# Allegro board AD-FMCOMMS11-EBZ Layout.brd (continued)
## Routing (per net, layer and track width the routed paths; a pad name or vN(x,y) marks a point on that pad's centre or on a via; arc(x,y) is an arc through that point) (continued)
AVDD1P3_ADC: length 33.7
  TOP w0.305: U101.C14 v1(50.01,55.58) U101.D14 v1(50.41,55.18) U101.D13 v1(50.41,54.38) U101.D12 v1(50.81,53.98) U101.E12 v1(51.61,53.98) U101.F12 v1(52.41,53.98) U101.G12 v1(53.21,53.98) U101.H12 v1(54.01,53.98) U101.J12 ; U101.A4 v1(48.41,47.98) U101.B5 v1(49.21,48.78) U101.C6 v1(50.01,49.58) U101.D7 v1(50.81,49.98) U101.E7 v1(51.61,49.98) U101.F7 v1(52.41,49.98) U101.G7 v1(53.21,49.98) U101.H7 v1(54.01,49.98) U101.J7
  TOP w0.406: 76.7,60.44 C234.1 77.36,59.78
  TOP w0.635: 76.18,64.86 TP12.1 75.44,64.12 ; 77.53,63.1 E23.2 76.61,64.1 ; C229.1 76.8,62.76 ; C229.1 76.8,60.86 ; C229.1 77.7,61.81
  BOTTOM w0.305: 50.48,55.58 v1(50.01,55.58) 49.96,55.52 C287.1 ; 50.48,55.58 C300.1 ; 50.48,55.58 50.48,55.24 v1(50.41,55.18) 50.36,55.12 C294.1 50.36,54.44 ; 50.36,54.44 v1(50.41,54.38) 50.41,53.99 50.4,53.98 ; 50.36,54.44 C279.1 50.4,53.98 ; v1(49.21,48.78) 49.21,48.79 49.34,48.92 C262.1 ; C275.1 48.13,47.7 v1(48.41,47.98) 48.59,48.16 C272.1 ; 50.4,53.98 v1(50.81,53.98) 50.83,54 C303.1 51.59,54 v1(51.61,53.98) 51.63,54 C305.1 52.39,54 v1(52.41,53.98) 52.43,54 C297.1 53.19,54 v1(53.21,53.98) 53.23,54 C307.1 53.99,54 v1(54.01,53.98) 54.03,54 C283.1 ; v1(50.81,49.98) 50.86,49.93 C198.1 51.57,49.93 v1(51.61,49.98) 51.66,49.93 C200.1 52.37,49.93 v1(52.41,49.98) 52.46,49.93 C290.1 53.17,49.93 v1(53.21,49.98) 53.26,49.93 C268.1 53.97,49.93 v1(54.01,49.98) 54.03,50 C258.1
  vias: v3(76.58,60.67) v3(77.22,60.67) v3(77.85,62.32) v3(77.85,61.68) v3(77.85,61.05) v3(77.85,60.41) v3(77.85,59.78)
AVDD2P5_ADC: length 35.6
  TOP w0.305: U101.A6 v1(48.41,49.58) U101.B7 v1(49.21,50.38) U101.C8 v1(50.01,50.78) U101.D8 v1(50.81,50.78) U101.E8 v1(51.61,50.78) U101.F8 v1(52.41,50.78) U101.G8 v1(53.21,50.78) U101.H8 v1(54.01,50.78) U101.J8 ; v3(43.73,47.39) 44.14,47.39 44.32,47.2 TP17.1 ; U101.A14 v1(48.01,55.18) U101.A13 U101.B12 v1(49.21,53.58) U101.C11 v1(50.01,53.18) U101.D11 v1(50.81,53.18) U101.E11 v1(51.61,53.18) U101.F11 v1(52.41,53.18) U101.G11 v1(53.21,53.18) U101.H11 v1(54.01,53.18) U101.J11
  BOTTOM w0.305: 51.54,53.11 C264.1 52.34,53.11 ; 51.54,53.11 C261.1 50.88,53.11 ; 51.54,53.11 v1(51.61,53.18) ; C304.1 48.07,55.12 v1(48.01,55.18) 48.07,55.24 C278.1 ; 53.28,53.11 v1(53.21,53.18) 53.14,53.11 ; 53.28,53.11 C270.1 53.94,53.11 ; 53.28,53.11 53.14,53.11 ; 49.94,53.11 v1(50.01,53.18) 50.08,53.11 ; 49.94,53.11 50.08,53.11 ; 49.94,53.11 C257.1 ; 50.74,53.11 v1(50.81,53.18) 50.88,53.11 ; 50.74,53.11 50.88,53.11 ; 50.74,53.11 C259.1 50.08,53.11 ; v1(49.21,50.38) C308.1 ; 54.08,53.11 53.94,53.11 ; 54.08,53.11 v1(54.01,53.18) 53.94,53.11 ; 54.08,53.11 C274.1 ; 52.34,53.11 v1(52.41,53.18) 52.48,53.11 ; 52.34,53.11 52.48,53.11 ; 52.48,53.11 C267.1 53.14,53.11 ; C302.1 54.31,50.78 v1(54.01,50.78) 53.64,50.78 C299.1 53.55,50.78 v1(53.21,50.78) 52.88,50.78 C296.1 52.79,50.78 v1(52.41,50.78) 52.11,50.78 C293.1 52.03,50.78 v1(51.61,50.78) 51.35,50.78 C289.1 51.26,50.78 v1(50.81,50.78) 50.59,50.78 C285.1 50.5,50.78 v1(50.01,50.78) 49.83,50.78 C281.1 ; v1(48.41,49.58) 48.16,49.58 C306.1 ; C309.1 49.05,53.74 v1(49.21,53.58)
  BOTTOM w0.508: 42.79,47.18 C256.1 ; C256.1 43.45,47.84 ; C256.1 42.79,48.5
  BOTTOM w0.635: C253.1 43.14,46.89 ; C253.1 44.04,45.93 ; C253.1 43.14,44.98
  BOTTOM w0.762: 41.21,44.39 E30.2 42.14,43.39
  vias: v3(42.97,48.66) v3(43.73,48.66) v3(43.73,48.02)
AVDD3P3_4355: length 19.2
  TOP w0.305: 35.18,31.18 TP23.1 34.44,30.44 ; v1(41.53,33.49) 41.78,33.23 41.78,33.04 C329.1 ; C331.1 42.35,37.36 v1(42.54,37.55)
  TOP w0.508: 33.5,27.63 C160.1 ; C160.1 34.82,27.63 ; C160.1 34.16,28.29
  TOP w0.635: E18.2 33.25,30.44 ; E18.2 32.32,29.45 ; E18.2 32.32,31.43 ; 32.26,28.89 C153.1 33.21,27.99
  BOTTOM w0.203: v1(38.36,38.94) 38.35,38.94 U18.5
  BOTTOM w0.254: v1(44.32,38.31) L14.2 ; C36.1 45.87,31.86 v1(45.47,31.46) L15.2 ; L16.2 v1(43.62,29.61) 43.23,29.22 C13.1 ; v1(44.32,35.76) L13.2
  BOTTOM w0.305: U18.10 41.12,36.77 C332.1 41.92,37.55 v1(42.54,37.55) ; U18.16 41.25,33.77 v1(41.53,33.49) ; C315.1 44.32,35.2 v1(44.32,35.76) ; C314.1 v1(44.32,38.31)
  BOTTOM w0.508: C330.1 C329.1 41.53,33.3 v1(41.53,33.49)
  vias: v3(33.53,28.79) v3(34.16,28.79) v3(34.8,28.79)
DVDD1P3_ADC: length 19
  TOP w0.305: U101.D1 v1(50.41,45.58) U101.D2 v1(50.41,46.38) U101.D3 ; U101.H1 v1(53.61,45.58) U101.H2 v1(53.61,46.38) U101.H3 ; U101.K1 v1(55.21,45.58) U101.K2 ; U101.F1 v1(52.01,45.58) U101.F2 v1(52.01,46.38) U101.F3
  BOTTOM w0.305: 51.88,46.51 v1(52.01,46.38) 51.88,46.25 ; 51.88,46.51 51.88,46.25 ; 51.88,46.51 C273.1 ; 51.88,46.25 C277.1 51.88,45.71 ; C295.1 53.53,46.46 ; 53.53,46.46 53.53,46.3 ; 53.53,46.46 v1(53.61,46.38) 53.53,46.3 ; 51.88,45.71 v1(52.01,45.58) 51.88,45.45 ; 51.88,45.71 51.88,45.45 ; 53.53,45.66 C298.1 53.53,46.3 ; 53.53,45.66 53.53,45.5 ; 53.53,45.66 v1(53.61,45.58) 53.53,45.5 ; C284.1 50.36,46.44 v1(50.41,46.38) 50.36,46.32 C288.1 50.36,45.64 v1(50.41,45.58) 50.36,45.52 C292.1 ; 51.88,45.45 C280.1 ; 53.53,45.5 C301.1 ; C269.1 55.21,45.2 v1(55.21,45.58) 55.21,45.9 C266.1
  BOTTOM w0.508: 63.49,54.16 C236.1 ; C236.1 63.49,55.49 ; C236.1 64.15,54.82
  BOTTOM w0.635: 66.48,54.34 E25.2 ; E25.2 66.48,56.32 ; E25.2 65.56,55.33 ; 64.49,56.73 C231.1 63.59,55.78
  vias: v3(64.64,56.6) v3(65.28,56.6) v3(65.91,56.6) v3(66.67,63.33) v3(66.67,56.6)
DVDD2P5_ADC: length 16.1
  TOP w0.254: U24.14 105.28,47.95 105.79,48.46 C126.2
  TOP w0.305: v3(106.3,30.95) C98.2 105.52,30.95 105.41,31.06 105.41,31.46 105.03,31.84 U14.10 ; U101.E4 v1(50.81,47.18) ; v3(105.79,49.36) C126.2
  TOP w0.508: 55.9,41.49 TP19.1 ; TP19.1 56.64,40.75 ; TP19.1 56.64,42.23 ; C255.1 55.23,42.15 ; C255.1 55.23,40.83 ; C255.1 55.89,41.49 ; E14.1 v3(21.72,43.65)
  TOP w0.635: C252.1 55.71,40.54 ; C252.1 55.71,38.63 ; C252.1 56.62,39.58 ; 56.87,37.36 E29.2 55.88,38.29
  BOTTOM w0.305: C199.1 50.5,47.46 50.77,47.18 v1(50.81,47.18)
  vias: v3(56.13,43.01) v3(56.13,42.38) v3(56.78,43.01) v3(56.77,42.38)
DVDD3P3_4355: length 8.1
  TOP w0.508: 45.85,36.31 C151.1 46.8,37.21 ; 43.28,36.55 C158.1 44.6,36.55
  BOTTOM w0.203: U18.4 37.85,38.89 v1(37.79,38.95)
  BOTTOM w0.305: U18.26 34.9,34.27 v3(34.8,34.38) ; v3(34.8,34.38) 34.28,33.86 C328.1 33.77,34.25 C15.1 ; v3(34.8,34.38) 35.19,34.77 U18.27
  vias: v3(42.42,35.39) v3(42.93,35.9)
DVDD12_DAC: length 19.4
  TOP w0.254: U1.G7 v2(53.22,19.34) ; v2(54.72,21.34) v2(54.72,20.84) v2(54.72,20.34) v2(54.72,19.84) v2(54.72,19.34) ; v2(53.22,21.34) U1.G9
  TOP w0.305: TP2.1 v3(60.07,32.73)
  TOP w0.508: v3(47.88,24.34) 47.5,24.73 47.37,24.73 ; 47.37,24.73 47.5,24.85 v3(47.5,25.49) 47.5,26.54 C119.1 ; 47.37,24.73 C78.1
  BOTTOM w0.254: C116.1 53.22,19.07 v2(53.22,19.34) ; C124.1 53.22,21.75 v2(53.22,21.34)
  BOTTOM w0.305: U27.9 60.41,31.12 60.26,31.27 60.26,31.9 ; 54.74,19.83 54.74,20.34 C120.1 54.74,20.47 54.74,20.83 v2(54.72,20.84) 54.74,20.86 54.74,21.11 C131.1 54.72,21.25 v2(54.72,21.34) ; 54.74,19.83 v2(54.72,19.84) ; 54.74,19.83 54.8,19.76 C123.1 54.8,19.42 v2(54.72,19.34) ; 60.34,33.07 U27.12 61.22,33.6 ; 60.34,32.42 U27.11 ; U27.14 62.79,34.87 ; 61.61,33.99 U27.13 62.14,34.87 ; 60.34,31.77 U27.10
  BOTTOM w0.635: C85.1 58.99,35.05 ; C85.1 58.99,33.45 ; C85.1 59.73,34.25
  vias: v3(58.8,32.73) v3(59.44,32.73) v3(60.07,33.36)
DVDDIO3P3_ADC: length 11.6
  TOP w0.305: v1(52.41,47.98) U101.F4 v1(51.61,47.98) U101.F5 52.01,48.38 v1(52.41,47.98) ; v1(52.41,47.98) U101.G5
  TOP w0.508: 49.52,35.55 C237.1 50.18,34.89 ; 51.54,33.36 C232.1 50.63,34.31 ; 51.16,36.98 E26.2 50.16,36.05
  BOTTOM w0.254: R101.1 v1(55.88,44.66)
  BOTTOM w0.305: C282.1 52.77,48.33 v1(52.41,47.98) 52.12,47.98 C286.1 52.01,47.97 51.63,47.97 v1(51.61,47.98) 51.37,48.22 C291.1
  BOTTOM w0.508: v3(50.29,35.77) v3(49.53,35.77)
GND: length 1139.7
  TOP w0.152: U1.H15 U1.G14
  TOP w0.203: U1.A13 v2(50.22,23.34) 49.77,23.34 v3(49.28,23.84)
  TOP w0.229: C9.2 v3(15.37,23.33)
  TOP w0.254: U1.D13 U1.D14 ; U1.D13 51.72,22.49 ; U1.D13 v2(52.22,22.84) ; U1.D14 v2(52.22,23.34) v2(52.22,22.84) ; U1.D14 U1.D15 ; v2(53.72,21.34) v2(53.72,20.84) v2(53.72,20.34) v2(53.72,19.84) v2(53.72,19.34) U1.H3 v2(53.22,17.84) ; U25.12 30.84,49.46 ; U25.12 30.33,50.14 ; U25.12 30.33,48.75 ; U25.21 29.33,52.66 v1(29.08,52.41) ; U1.N6 v2(56.22,19.84) ; v1(18.54,18.88) 18.55,18.87 U16.3 ; v1(18.03,21.42) 18.05,21.44 U16.23 18.05,23.35 18.16,23.46 ; v2(52.22,17.84) 52.22,18.27 52.72,18.77 v2(52.72,19.34) v2(52.72,19.84) v2(52.72,20.34) ; v2(52.22,17.84) U1.E2 ; v2(52.22,17.84) U1.D3 v2(51.72,17.59) U1.D2 ; v2(54.22,21.34) v2(54.22,20.84) v2(54.22,20.34) v2(54.22,19.84) v2(54.22,19.34) ; v1(30.1,52.41) 30.33,52.65 U25.19 ; 27.83,48.75 U25.7 ; U25.7 27.83,50.14 ; U25.7 27.32,49.46 ; U101.M5 v1(56.81,48.78) U101.M6 ; v1(29.59,50.38) 29.83,50.14 U25.11 29.83,48.75 ; v1(20.07,18.88) 20.05,18.87 U16.6 ; v1(34.92,62.57) 34.68,62.32 U17.6 ; U1.E2 U1.E1 52.22,16.32 v4(52.48,16.06) ; U1.E2 U1.D2 ; v1(20.07,21.42) 20.05,21.44 U16.19 ; v1(18.54,21.42) 18.55,21.44 U16.22 ; 104.78,49.89 U23.7 104.27,50.73 ; 56.41,45.18 56.42,45.18 ; 56.41,45.18 U101.L1 ; 56.41,45.18 v4(56.41,45.17) 56.42,45.18 ; 56.42,45.18 U101.M1 ; v1(20.57,20.41) 20.58,20.4 U16.13 ; U25.20 29.83,52.65 v1(29.59,52.41) ; U16.11 20.59,19.4 v1(20.57,19.39) ; v2(52.72,20.34) v2(52.72,20.84) v2(52.72,21.34) 52.72,21.94 52.67,21.99 52.26,21.99 ; v2(52.72,20.34) U1.G8 ; U101.M4 v4(56.81,47.18) U101.M3 ; U1.H13 v2(53.22,22.84) U1.G14 ; 52.22,22.49 v2(52.22,22.84) ; U16.2 18.05,18.86 v1(18.03,18.88) 17.91,18.88 17.43,18.4 U16.32 ; U101.B11 v1(48.41,53.18) U101.A11 ; 21.05,18.4 v1(20.57,18.88) 20.55,18.86 U16.7 ; 21.05,18.4 U16.8 ; 21.05,18.4 U16.9 ; U13.2 103.73,40.06 ; U1.P1 56.72,16.52 56.77,16.47 v2(56.77,16.22) ; 30.33,50.14 U25.13 ; 30.33,50.14 v1(30.1,50.38) ; U25.13 31.73,50.14 ; U25.13 31.01,49.64 ; U1.D2 U1.C2 U1.B2 U1.B1 50.72,16.37 v4(50.44,16.09) ; v1(20.57,21.42) 21.05,21.9 ; v1(20.57,19.9) 20.58,19.9 U16.12 ; 27.83,50.14 v1(28.07,50.38) ; 27.83,50.14 U25.6 ; v1(28.58,52.41) 28.83,52.67 U25.22 ; U16.18 20.55,20.94 v1(20.57,20.92) ; 52.81,45.58 v1(52.81,45.58) ; 103.73,36.57 U13.7 ; 105.79,43.87 U24.8 105.28,43.03 ; U1.G2 v2(53.22,17.84) ; v2(53.22,17.84) 53.22,18.2 ; v1(26.54,29.04) v1(26.03,29.55) 25.78,29.29 U15.6 ; 104.28,36.52 U13.8 104.78,35.69 ; 105.77,36.52 U13.9 105.28,35.69 ; U1.R5 v2(57.75,18.84) ; U16.20 19.55,21.43 v1(19.56,21.42) ; U1.R2 v2(57.64,17.34) ; v2(55.22,16.3) U1.L1 v2(55.22,17.34) ; U1.R11 v2(57.75,21.84) ; U20.4 64.78,35.15 65.02,35.39 ; v3(22.73,52.03) 22.86,51.9 v3(24.26,51.9) v3(25.15,51.9) 25.27,51.78 26.1,51.78 26.73,51.14 U25.4 27.82,51.14 v1(28.07,51.4) ; 105.79,50.73 U23.8 105.28,49.89 ; U1.R8 v2(57.72,20.34) ; U1.H1 53.72,16.34 v2(53.59,16.22) 53.39,16.01 ; U16.14 20.08,20.9 v1(20.07,20.92) ; v1(55.22,24.3) U1.L15 ; U25.23 28.33,52.68 v1(28.07,52.41) 27.83,52.65 ; 106.34,50.78 U23.9 ; v1(30.1,51.4) 30.35,51.14 U25.15 ; 27.83,52.65 U25.24 ; 27.83,52.65 U25.1 ; 28.33,48.75 U25.8 28.33,50.14 v1(28.58,50.38) 28.83,50.12 U25.9 28.83,48.75 ; U101.C5 v1(50.01,48.38) U101.D5 ; U101.K5 v1(55.61,48.38) U101.L5 ; U1.P15 v1(56.72,24.43) ; U16.5 19.55,18.88 v1(19.56,18.88) ; U10.6 7.24,14.56 v1(7.49,14.31) ; 104.78,43.03 U24.7 104.27,43.87 ; v1(29.08,50.38) 29.33,50.13 U25.10 29.33,48.75 ; U1.R14 v2(57.77,23.34)
  TOP w0.305: 18.92,12.7 C21.2 ; C21.2 18.34,13.23 ; C21.2 19.51,13.23 ; TP14.1 8.38,38.06 ; TP14.1 7.62,38.82 ; TP14.1 6.86,38.06 ; TP14.1 7.62,37.3 ; TP25.1 68.58,60.79 ; TP25.1 67.82,60.03 ; TP25.1 69.34,60.03 ; TP25.1 68.58,59.27 ; 49.21,51.58 v4(49.21,51.58) ; 49.21,51.58 v4(49.21,51.58) ; 49.21,51.58 U101.C9 ; v4(49.21,51.58) U101.B9 ; 78.27,6.82 R22.2 ; R22.2 78.8,7.4 ; R22.2 78.8,6.23 ; C20.2 21.01,13.05 ; C20.2 20.32,12.37 ; C20.2 19.63,13.05 ; R27.2 63.06,10.7 ; R27.2 63.06,9.54 ; R27.2 63.59,10.12 ; v3(104.14,30.06) U8.7 104.14,27.06 ; U101.K7 v1(55.21,50.38) U101.K8 ; U101.K7 55.21,49.58 ; U101.K7 U101.L7 ; U101.C10 U101.C9 ; U101.C10 49.21,52.38 ; U101.C10 v1(50.01,52.38) U101.D10 ; U101.C9 v1(50.01,51.58) U101.D9 ; C334.1 39.41,12.53 ; C334.1 38.72,13.22 ; C334.1 38.72,11.85 ; 48.81,51.99 v4(48.81,51.98) 48.81,51.97 ; 48.81,51.99 48.81,51.97 ; 48.81,51.99 U101.B10 ; 56.41,48.38 U101.L5 56.01,48.78 ; 56.41,48.38 U101.M5 v4(56.81,47.98) U101.M4 ; 56.41,48.38 v4(56.41,48.38) ; 54.22,18.84 v2(54.22,19.34) v2(53.72,19.34) ; U101.B9 U101.B8 v4(48.41,50.78) U101.A8 47.45,50.78 ; U101.B9 48.81,51.97 ; v4(18.29,16.6) v4(18.29,15.96) 18.29,15.58 v4(18.41,15.45) 18.54,15.33 v4(19.05,15.33) v4(19.56,15.33) v4(20.07,15.33) v4(20.57,15.33) v4(21.08,15.33) ; 18.92,62.37 C22.1 ; C22.1 20.1,63.4 ; C22.1 17.74,63.4 ; U101.L8 U101.M8 ; U101.L8 56.01,50.38 ; U101.L8 U101.K8 ; U101.M8 v4(56.81,50.38) U101.M7 ; U101.M8 v4(56.81,51.18) U101.M9 v1(56.81,51.98) U101.M10 ; v1(18.54,20.92) v1(19.05,20.41) U16.PAD v1(19.56,19.9) v1(20.07,19.39) v1(20.57,18.88) ; 36.39,54.01 T5.3 37.59,53.25 ; C97.1 103,49.39 ; C97.1 102.17,48.6 ; C97.1 103,47.81 ; 72.9,40.6 TP8.1 ; TP8.1 74.42,40.6 ; TP8.1 73.66,39.84 ; TP8.1 73.66,41.36 ; 107.24,3.53 R67.1 106.55,2.84 ; v2(54.22,20.34) v2(53.72,20.34) ; 28.32,36.62 C145.2 ; C145.2 27.63,37.31 ; C145.2 29.01,37.31 ; 68.14,1.11 Q1.2 ; 101.99,30.13 C83.2 ; C83.2 101.99,31.51 ; C83.2 101.31,30.82 ; C47.2 67.74,9.88 ; C47.2 67.06,9.19 ; C47.2 66.37,9.88 ; 103.38,59.65 TP26.1 ; TP26.1 104.9,59.65 ; TP26.1 104.14,58.89 ; TP26.1 104.14,60.41 ; v1(19.81,23.33) 20.05,23.09 U16.19 ; v1(19.81,23.33) 19.86,23.33 20.45,23.91 20.45,23.96 ; v1(19.81,23.33) 19.62,23.13 19.55,22.9 U16.20 ; 38.72,10.68 C310.1 39.41,9.99 ; 102.17,41.74 C90.1 ; C90.1 103,40.96 ; C90.1 103,42.53 ; 49.2,54.78 v4(49.21,54.78) 49.21,54.78 ; 49.2,54.78 U101.B13 v1(48.81,55.18) U101.B14 48.81,56.14 ; 49.2,54.78 49.21,54.78 ; 12.7,61.43 TP9.1 ; TP9.1 13.46,62.19 ; TP9.1 11.94,62.19 ; TP9.1 12.7,62.95 ; 36.21,32.88 R9.1 ; R9.1 36.89,33.56 ; R9.1 36.89,32.19 ; U101.J9 v1(54.01,51.58) U101.H9 ; U101.J9 U101.K9 ; U101.J9 U101.J10 ; 56.01,50.38 v4(56.01,50.38) ; 56.01,50.38 v4(56.01,50.38) ; U101.K13 v1(55.21,54.38) U101.K12 v1(55.21,53.58) U101.K11 v1(55.21,52.78) U101.K10 ; U101.K13 55.61,54.78 ; U101.K13 54.81,54.78 ; 25.02,54.79 C338.2 24.43,54.25 ; U8.4 106.68,24.93 ; U8.4 107.37,23.46 ; U8.4 106.68,21.98 ; 73.72,9.32 C69.1 ; C69.1 73.72,11.68 ; C69.1 74.75,10.5 ; v4(56.01,50.38) U101.L7 ; 55.71,21.34 v2(56.22,21.34) ; 67.64,34.01 C248.2 ; C248.2 69.01,34.01 ; C248.2 68.33,33.32 ; U101.C7 v1(49.21,49.58) 48.81,49.18 U101.B6 v1(48.41,48.78) U101.A5 47.45,48.38 ; U101.G3 U101.G2 U101.G1 52.81,44.62 ; 36.65,45.69 R121.2 37.34,45.01 ; U101.K9 v1(55.21,51.18) U101.K8 ; U101.K9 v1(55.21,51.98) U101.K10 ; 25.22,54.81 C337.2 26.59,54.81 ; U101.K5 55.37,48.54 55.37,49.02 U101.K6 v4(55.21,49.58) ; 55.61,54.78 55.62,54.78 ; 55.61,54.78 v4(55.61,54.78) 55.62,54.78 ; 47.45,45.98 U101.A2 ; U101.A2 U101.A3 47.45,46.78 ; U101.A2 U101.A1 ; U101.E9 v1(51.61,51.58) U101.F9 ; U101.E9 U101.E10 ; U101.E9 v1(50.81,51.58) U101.D9 ; U14.7 v3(103.8,33.23) ; U25.15 31.73,51.14 ; U101.P12 v1(58.81,54.38) ; U101.H13 v1(53.21,54.78) U101.G13 v1(52.41,54.78) U101.F13 v1(51.61,54.78) U101.E13 v1(51.21,55.18) U101.E14 51.21,55.94 v4(51.05,56.09) ; U101.H13 v1(54.01,54.78) U101.J13 54.81,54.78 ; U101.H13 U101.H14 53.61,55.86 v4(53.85,56.09) 53.85,56.35 54.14,56.64 54.14,56.67 54.42,56.95 54.44,56.95 54.48,56.98 v4(54.48,57.11) ; 14.78,22.88 C9.2 ; 22.22,45.43 TP15.1 ; TP15.1 22.22,46.95 ; TP15.1 22.99,46.19 ; TP15.1 21.46,46.19 ; U101.C12 v1(49.61,54.38) U101.C13 49.21,54.78 ; 55.62,54.78 U101.L13 U101.L14 ; U16.11 22.58,19.4 ; 54.22,21.7 v2(54.22,21.34) v2(53.72,21.34) 53.72,21.8 53.22,22.3 v2(53.22,22.84) ; 48.01,44.62 U101.A1 ; U101.A1 U101.B1 ; U101.A1 47.45,45.18 ; 102.17,55.33 C94.1 103,56.12 ; 41.33,38 C331.2 41.91,38.53 ; U101.F9 U101.F10 ; U101.F9 v1(52.41,51.58) U101.G9 ; U25.21 29.33,54.04 ; U25.1 27.15,53.15 ; C320.1 v3(42.21,51.98) ; U101.M7 v4(56.81,49.58) U101.M6 U101.L6 ; U101.M7 U101.L7 ; v1(27.05,41.62) 27.29,41.86 U12.4 27.99,42.39 ; U101.L6 v4(56.01,48.78) ; U101.L6 v4(56.01,49.58) ; U101.E10 v1(50.81,52.38) U101.D10 ; U101.E10 v1(51.61,52.38) U101.F10 ; 70.52,30.22 R15.1 ; R15.1 72.48,30.22 ; R15.1 71.5,29.3 ; 30.33,54.04 U25.19 30.84,53.33 ; 49.21,52.38 U101.B10 ; 49.21,52.38 v4(49.21,52.38) ; v1(57.21,44.78) 56.94,44.78 56.81,44.91 U101.M1 v4(56.81,45.58) U101.M2 56.9,46.06 56.9,46.7 U101.M3 ; U101.K10 U101.J10 ; 21.64,22.6 21.75,22.49 U16.16 21.05,21.9 U16.17 ; 50.8,28.07 C10.2 51.49,27.38 ; U101.H9 U101.H10 ; U101.H9 v1(53.21,51.58) U101.G9 ; U101.B1 U101.C1 ; U101.B1 v1(48.81,45.58) U101.B2 v1(48.81,46.38) U101.B3 v1(48.81,47.18) U101.B4 ; U101.B1 48.81,44.62 ; 107.06,42.53 C125.1 107.89,41.74 ; U101.G10 v1(53.21,52.38) U101.H10 ; U101.G10 U101.G9 ; U101.G10 v1(52.41,52.38) U101.F10 ; 56.01,48.78 v4(56.01,48.78) ; 56.01,48.78 v4(56.01,48.78) ; 71.08,60.41 R113.2 71.77,61.1 ; v4(55.21,49.58) 55.21,49.58 ; v4(55.21,49.58) 55.21,49.58 ; U101.D9 U101.D10 ; U101.L7 56.01,49.58 ; U101.B10 U101.B11 ; 106.34,43.92 U24.9 ; 22.94,43.25 C146.2 ; C146.2 24.31,43.25 ; C146.2 23.62,43.94 ; U101.M14 56.81,56.14 ; U101.M14 v1(57.21,55.98) ; U101.M14 U101.L14 ; 64.08,34.62 U20.4 ; 106.81,49.36 v3(106.68,49.36) ; v3(59.44,1.36) 59.44,1.74 58.93,2.25 U21.5 ; C188.2 v4(52.87,13.3) ; 28.81,46.06 DS1.C ; DS1.C 29.64,45.29 ; DS1.C 29.64,46.84 ; U101.D5 U101.D6 v1(50.81,49.18) U101.E6 v1(51.61,49.18) U101.F6 v1(52.41,49.18) U101.G6 v1(53.21,49.18) U101.H6 ; U101.C1 v1(49.61,45.58) U101.C2 v1(49.61,46.38) U101.C3 v1(49.61,47.18) U101.C4 ; U101.C1 49.61,44.62 ; U101.H10 v1(54.01,52.38) U101.J10 ; 81.83,66.89 C226.2 82.36,67.47 ; 12.7,6.82 TP16.1 ; TP16.1 11.94,7.58 ; TP16.1 13.46,7.58 ; TP16.1 12.7,8.34 ; U25.22 28.83,54.04 ; 107.44,30.12 C92.1 108.23,30.95 ; C72.1 73.72,8.89 ; U25.23 28.33,54.04 ; 54.81,54.78 v4(54.81,54.78) 54.81,54.78 ; 54.81,54.78 54.81,54.78 ; U16.17 21.05,23.43 ; U16.17 21.59,22.6 ; U1.D15 51.72,24.35 ; U101.L14 56.01,56.14 ; 53.72,22.49 U1.H13 ; 61.56,6.09 C321.2 ; U101.J1 v1(54.41,45.58) U101.J2 U101.J3 ; U26.9 104.02,16.16 v3(103.84,16.34) ; 27.15,49.64 U25.6 ; C329.2 42.49,32.28 ; C329.2 41.33,32.28 ; C329.2 v4(41.91,31.84) ; 105.41,24.93 U8.3 105.41,21.98 ; C98.1 v3(103.76,30.95) ; C126.1 107.06,49.39 ; 52.37,5.29 T4.2 v3(52.37,2.5) ; 47.45,53.18 U101.A11 ; 103.84,33.73 U14.6 104.43,34.26 ; 107.07,56.12 C103.1 107.9,55.33 ; 55.71,19.34 U1.N6 ; U25.20 29.83,54.04 ; v4(56.01,49.58) 56.01,49.58 ; v4(56.01,49.58) 56.01,49.58 ; U101.E3 v1(51.21,46.38) U101.E2 v1(51.21,45.58) U101.E1 51.21,44.62 ; R37.2 v3(57.53,66.25) ; C164.2 38.75,62.62 ; C164.2 38.06,61.94 ; C164.2 38.75,61.25 ; C1.2 37.85,22.69 v4(37.34,23.2) ; v1(83.69,64.35) 84.02,64.67 VR2.6 84.02,66.39 ; U14.5 v3(105.03,34.5) ; 55.71,19.84 v2(56.22,19.84) ; C203.1 v3(52.41,59.14) ; 27.32,53.33 U25.24 27.83,54.04 ; 100.79,7.08 R56.1 ; U16.22 18.55,22.92 18.5,23.12 v1(18.29,23.33) 18.16,23.46 v1(17.78,23.46) ; U26.6 v3(106.24,15.31) ; U16.18 20.55,23.43 ; C189.2 v3(50.08,13.3) ; v2(54.22,19.84) v2(53.72,19.84) ; v3(45.21,24.98) 45.47,24.73 C78.2 46.11,25.41 ; v2(54.22,20.84) v2(53.72,20.84) ; v1(23.5,64.86) v1(24,64.86) 24.25,65.1 U3.8 25.05,65.71 ; U16.12 22.58,19.9 ; T5.2 37.59,51.98
  TOP w0.381: v1(98.52,14.11) 98.74,14.11 ; v1(99.84,11.57) 100.02,11.57 ; v1(99.84,16.65) 100.01,16.65
  TOP w0.406: 75.02,59.78 C234.2 75.7,59.09
  TOP w0.508: R35.1 v3(104.01,6.31) ; C254.2 60.95,42.18 ; C254.2 60.95,40.8 ; C254.2 61.63,41.49 ; 48.53,35.57 C237.2 47.84,34.89 ; 62.9,40.56 C247.2 ; C247.2 64.86,40.56 ; C247.2 63.88,41.49 ; R47.1 v3(102.74,6.31) ; FL1.2 v3(30.23,22.44) ; T5.3 v3(35.05,53.25) ; C154.2 100.9,20.06 ; C154.2 100.9,17.7 ; C154.2 99.87,18.88 ; 44.87,38.91 C151.2 45.85,39.84 ; 102.12,16.29 C129.1 101.43,16.98 ; FL1.4 v3(30.23,20.28) ; 18.54,33.87 T6.2 20.96,33.87 ; 32.4,36.61 C159.2 ; C159.2 32.4,37.98 ; C159.2 31.71,37.3 ; C119.2 45.89,27.61 ; C119.2 45.89,25.65 ; C119.2 44.96,26.63 ; 43.26,37.54 C158.2 ; v3(67.19,1.75) Q1.2 ; R56.1 v3(101.47,6.31) ; C160.2 34.85,26.64 ; C160.2 33.48,26.64 ; C160.2 34.16,25.96 ; 61.85,33.74 C250.2 62.83,34.67 ; T5.2 v3(35.05,51.98) ; 48.01,33.36 C232.2 48.93,32.38 ; R38.1 v3(105.28,6.31) ; 54.24,40.8 C255.2 ; C255.2 54.24,42.18 ; C255.2 53.56,41.49 ; 65.28,38.95 C243.2 ; C243.2 66.21,39.93 ; C243.2 66.21,37.97 ; 61.89,8.72 C322.2 61.2,9.41 ; R51.1 v3(106.55,6.31)
  TOP w0.635: C228.2 80.86,59.43 ; C228.2 78.9,59.43 ; C228.2 79.88,58.51 ; 29.84,37.81 C147.2 30.82,38.73 ; 60.92,38.61 C251.2 ; C251.2 60.92,40.56 ; C251.2 61.85,39.58 ; 23.24,25.74 C140.2 ; C140.2 22.26,26.67 ; C140.2 24.22,26.67 ; C143.2 29.84,45.05 ; C143.2 30.82,44.12 ; C143.2 28.87,44.12 ; T3.1 52.04,68.03 ; T3.1 51.28,66.83 ; T3.1 52.04,65.62 ; 56.68,9.27 C117.1 ; C117.1 55.75,10.25 ; C117.1 56.68,11.23 ; 32.26,25.36 C153.2 ; C153.2 33.24,26.29 ; C153.2 31.28,26.29 ; C142.2 38.35,59.14 ; C142.2 37.43,58.16 ; C142.2 37.43,60.12 ; 106.01,19.33 C156.1 ; C156.1 108.37,19.33 ; C156.1 107.19,20.36 ; 15.02,13.59 C102.2 ; C102.2 16,12.66 ; C102.2 16.98,13.59 ; C148.2 30.95,26.29 ; C148.2 29.97,25.36 ; C148.2 28.99,26.29 ; 105.88,19.1 C128.1 104.9,20.03 ; C99.2 4.79,15.54 ; C99.2 2.83,15.54 ; C99.2 3.81,16.47 ; C316.2 60.07,5.68 ; C316.2 61.05,4.75 ; C316.2 59.09,4.75 ; C157.2 38.01,64.69 ; C157.2 38.01,62.74 ; C157.2 37.08,63.71 ; C206.2 88.48,59.43 ; C206.2 86.52,59.43 ; C206.2 87.5,58.51 ; 11.18,16.47 C101.2 10.2,15.54 ; C252.2 54.01,40.56 ; C252.2 53.09,39.58 ; C252.2 54.01,38.61 ; C317.2 57.49,5.76 ; C317.2 58.42,4.79 ; C317.2 57.49,3.81 ; C150.2 33.57,67.11 ; C150.2 33.57,65.15 ; C150.2 32.64,66.13 ; 17.69,40 C89.2 ; C89.2 18.67,39.08 ; C89.2 19.65,40 ; 31.11,39.2 C152.2 ; C152.2 32.04,38.22 ; C152.2 32.04,40.18 ; 53.31,68.03 T3.2 53.31,65.62 ; 75.1,60.83 C229.2 ; C229.2 75.1,62.79 ; C229.2 74.17,61.81
  TOP w0.762: C43.1 16.38,61.34 ; C43.1 17.77,60.16 ; C43.1 15,60.16 ; 22.26,38.86 C139.2 ; C139.2 24.22,38.86 ; C139.2 23.24,37.93 ; C50.1 19.43,61.34 ; C50.1 20.82,60.16 ; C50.1 18.05,60.16 ; 21.09,60.16 C45.1 ; C45.1 22.48,61.34 ; C45.1 23.86,60.16 ; 79.72,37.49 C54.1 ; C54.1 82.08,37.49 ; C54.1 80.9,36.46 ; 24.22,60.41 C38.1 25.4,61.8 ; C53.1 79.29,37.49 ; C53.1 76.92,37.49 ; C53.1 78.11,36.46
  TOP w1.016: 23.74,3.64 J5.2 ; J5.2 22.59,7.58 ; J5.2 23.74,11.52 ; 57.96,61.67 J2.3 ; J2.3 65.84,61.67 ; J2.3 61.9,60.53 ; 43.56,8.74 J3.2 47.5,7.59 ; J1.2 16.64,40.33 ; J1.2 12.7,39.19 ; J1.2 8.76,40.33 ; 26.54,39.53 v1(26.54,41.11) 26.54,42.68 ; 23.5,62.75 v1(23.5,64.35) ; 57.96,67.28 J2.2 65.84,67.28 ; J7.3 16.64,35.79 ; J7.3 8.76,35.79 ; J7.3 12.7,36.93 ; 47.5,1.98 v3(43.56,1.98) 39.62,1.98 ; 12.7,29.03 v3(12.7,30.17) ; v3(12.7,30.17) 16.64,30.17 ; v3(12.7,30.17) 8.76,30.17 ; 2.54,44.73 J6.2 5.46,46.38 ; 26.54,30.62 v1(26.54,29.04) 26.54,27.47 ; 29.35,3.64 v3(29.35,7.58) 30.49,7.58 ; 8.76,45.95 J1.3 ; J1.3 12.7,47.09 ; J1.3 16.64,45.95 ; 2.54,19.33 J4.2 5.46,20.98 ; 2.54,31.14 J4.4 5.46,29.49 ; 7.49,12.74 v1(7.49,14.31) 7.49,15.89 ; 5.46,54.89 J6.4 2.54,56.54 ; 36.5,62.57 v1(34.92,62.57) 33.35,62.57
  L11_GROUND w0.203: 35.81,38.82 35.83,38.84 35.83,39.35
  BOTTOM w0.203: P1.H12 v6(89.2,44.59) ; U2.4 74.3,32.85 74.61,32.54 74.87,32.54 v1(74.93,32.47) ; 92.37,56.66 v6(91.88,56.66) ; C14.2 v1(36.58,31.09) C5.2 ; P1.H3 v6(89.34,56.66) ; P1.D3 v6(94.42,56.66) ; P1.K3 v6(87.83,56.66) ; 87.29,49.04 v1(87.93,48.4) ; P1.G40 v3(90.47,9.03) ; 87.29,45.23 v6(87.93,44.59)
  BOTTOM w0.254: U6.12 76.98,10.1 ; 76.98,10.1 U6.13 ; 76.98,10.1 v1(77.22,9.87) ; v2(53.72,19.34) v2(53.72,19.84) ; C137.2 53.22,23.13 v2(53.22,22.84) ; C262.2 49.92,48.28 v1(50.01,48.38) ; v1(35.31,5.04) v1(35.81,5.55) 36.06,5.79 U7.4 ; U22.1 31.99,22.3 32.26,22.57 v3(32.26,22.95) ; v2(52.72,20.84) v2(52.72,21.34) 52.72,21.72 C124.2 ; C115.2 57.64,17.81 v2(57.64,17.34) ; v2(51.72,17.59) 51.72,17.75 51.82,17.84 52.22,17.84 v2(52.22,17.84) ; 54.17,21.93 54.05,21.93 53.72,21.6 v2(53.72,21.34) v2(53.72,20.84) ; R102.2 54.67,46.63 v1(54.41,46.38) ; v2(50.22,23.34) 50.1,23.46 C135.2 ; U6.7 76.98,7.6 v1(77.22,7.83) ; C116.2 52.64,19.26 v2(52.72,19.34) ; 67.37,24.16 U9.C2
  BOTTOM w0.305: 54.06,16.33 C134.2 ; C134.2 54.52,15.92 ; C134.2 54.98,16.33 ; C30.2 32.77,37.83 ; C30.2 32.07,37.17 ; C30.2 32.77,36.51 ; v1(39.12,34.5) 39.35,34.27 U18.18 ; C273.2 51.24,46.41 v1(51.21,46.38) 51.24,46.35 C277.2 51.24,45.61 v1(51.21,45.58) 51.24,45.55 C280.2 ; C74.2 37.07,2.68 ; C74.2 37.07,1.56 ; C74.2 37.63,2.12 ; 49.72,45.47 49.72,45.74 ; 49.72,45.47 v1(49.61,45.58) ; 49.72,45.47 C292.2 ; 49.72,45.74 49.61,45.64 v1(49.61,45.58) ; 49.72,45.74 C288.2 49.72,46.27 v1(49.61,46.38) ; C332.2 v3(41.15,38.56) ; C332.2 41.91,39.11 ; C332.2 42.47,38.56 ; 31.51,22.7 U22.1 30.59,22.3 ; 53.89,54.63 54.01,54.76 v1(54.01,54.78) 54.16,54.63 ; 53.89,54.63 54.16,54.63 ; 53.89,54.63 C307.2 53.36,54.63 ; P1.C13 v1(96.39,44.59) P1.C12 ; v1(52.41,52.38) 52.17,52.38 ; v1(52.41,52.38) v1(52.41,51.58) ; v1(52.41,52.38) 52.74,52.38 ; 52.17,52.38 51.97,52.38 ; 52.17,52.38 C264.2 51.97,52.38 ; 28.63,30.6 C18.2 ; C18.2 28.63,32.31 ; C18.2 29.43,31.46 ; P1.C4 v1(95.98,54.75) P1.C5 ; P1.E11 v3(93.01,47.13) ; 37.34,14.98 R84.1 36.78,14.43 ; 40.37,32.07 C327.2 40.2,31.33 C326.2 ; 92.37,49.04 v1(92.17,48.4) ; P1.B11 v1(97.66,47.13) P1.B10 ; 49.2,56.16 C287.2 ; C287.2 v3(49.66,56.73) ; C287.2 50.11,56.16 ; 51.4,52.38 U101.E10 ; 51.4,52.38 C261.2 U101.E10 ; 51.4,52.38 v1(51.61,52.38) ; U101.E10 v1(50.81,52.38) ; 89.83,14.75 v3(90.47,14.11) ; 43.56,57.29 U19.PAD ; U19.PAD 45.31,58.89 ; U19.PAD 43.56,60.49 ; U19.PAD 41.81,58.89 ; P1.A32 v1(98.52,19.19) P1.A33 ; 56.82,24.53 C118.2 ; C118.2 57.28,24.94 ; C118.2 57.87,24.53 v1(57.98,24.43) ; 94.91,51.58 v1(95.12,52.21) P1.D6 ; v1(49.61,46.38) v1(48.81,46.38) ; v1(49.61,46.38) 49.72,46.49 C284.2 49.72,47.07 ; P1.C20 96.18,34.93 v1(95.76,34.5) 96.18,34.08 P1.C21 ; 57.72,21.88 C108.2 58.13,21.42 ; 52.27,54.63 v1(52.41,54.78) 52.56,54.63 ; 52.27,54.63 52.56,54.63 ; 52.27,54.63 C305.2 51.76,54.63 ; v1(77.72,9.36) 77.48,9.6 U6.11 75.48,9.6 ; C120.2 54.17,20.79 v2(54.22,20.84) 54.17,20.9 C131.2 ; C120.2 54.17,20.4 ; C120.2 53.76,20.41 ; v1(50.81,51.58) 50.93,51.46 ; v1(50.81,51.58) 50.69,51.46 ; v1(50.81,51.58) v1(50.81,52.38) ; 50.93,51.46 50.69,51.46 ; 50.93,51.46 C289.2 51.49,51.46 ; v1(35.18,46.7) 35.11,46.77 VR3.6 v3(35.11,48.8) 35.12,48.81 C246.2 35.12,49.95 ; P1.A4 v3(99.36,54.75) P1.A5 99.79,53.05 v1(99.79,52.21) 99.79,51.38 ; 54.16,54.63 C283.2 54.81,54.63 ; 48.7,56.04 C278.2 48.7,55.29 ; C207.2 75.56,62.64 VR1.6 73.1,62.64 v1(73.03,62.57) ; C207.2 76.02,62.63 ; C207.2 75.56,63.04 ; 78,34.26 U2.13 79.01,33.85 v3(79.12,33.74) ; 49.72,47.07 49.72,47.29 ; 49.72,47.07 v1(49.61,47.18) 49.72,47.29 ; v1(64.64,10.37) 64.39,10.62 64.39,10.63 ; P1.C36 v1(96.39,14.11) ; 97.45,22.37 v3(98.09,23) ; 48.7,55.07 48.7,55.29 ; 48.7,55.07 C304.2 ; 48.7,55.07 v1(48.81,55.18) 48.7,55.29 ; R103.1 56.86,58.63 ; R103.1 56.01,59.43 ; R103.1 55.16,58.63 ; 52.2,16.25 C138.2 51.74,16.66 ; U5.2 64.39,10.63 ; 64.39,10.63 v1(64.64,10.88) ; 52.56,54.63 C297.2 53.07,54.63 ; v1(63.55,31.23) 63.44,31.12 U27.6 ; 39.85,37.27 v1(39.62,37.04) ; 39.85,37.27 U18.8 40.26,37.97 ; 39.85,37.27 U18.9 40.55,37.68 ; C36.2 46.65,31.73 ; C36.2 46,31.09 ; C36.2 46.61,31.12 ; P1.B3 v1(97.66,57.29) P1.B2 ; 48.77,52.7 C309.2 48.48,53.11 ; 97.45,10.94 v1(97.66,11.57) 97.45,12.21 ; 52.74,52.38 C267.2 52.93,52.38 ; 52.74,52.38 52.93,52.38 ; 50.69,51.46 C285.2 50.13,51.46 ; U2.9 75.7,35.39 v3(75.44,35.65) 75.2,35.41 U2.8 ; C136.2 56.44,16.24 ; C136.2 55.98,15.83 ; C136.2 55.52,16.24 ; 56.44,52.47 C276.2 ; C276.2 57.35,52.47 ; C276.2 56.9,52.07 ; P1.B15 v1(97.66,42.05) P1.B14 ; v1(39.12,35.01) 39.37,35.27 U18.13 41.52,35.27 v6(41.53,35.27) ; 59.55,19.97 C6.2 ; C6.2 60.11,20.53 ; C6.2 59.55,21.09 ; 50.64,52.38 50.45,52.38 ; 50.64,52.38 v1(50.81,52.38) ; 50.64,52.38 C259.2 50.45,52.38 ; 50.45,52.38 v1(50.01,52.38) ; 57.34,56.11 C260.2 57.34,56.81 ; 57.34,56.11 57.34,55.85 ; 57.34,56.11 v1(57.21,55.98) 57.34,55.85 ; 48.48,53.11 48.34,53.11 ; 48.48,53.11 v1(48.41,53.18) 48.34,53.11 ; 48.34,53.11 C144.2 ; 94.91,47.77 v1(95.23,47.13) ; 57.34,55.85 C263.2 ; 53.33,51.46 53.09,51.46 ; 53.33,51.46 v1(53.21,51.58) ; 53.33,51.46 C299.2 53.89,51.46 ; 53.09,51.46 v1(53.21,51.58) ; 53.09,51.46 C296.2 52.53,51.46 ; C144.2 47.88,52.7 ; C144.2 47.42,53.11 ; 53.69,52.38 C270.2 53.5,52.38 ; 53.69,52.38 53.5,52.38 ; 53.69,52.38 v1(54.01,52.38) ; v1(54.01,52.38) v1(54.01,51.58) ; v1(54.01,52.38) 54.26,52.38 C274.2 54.81,52.47 ; v1(54.01,51.58) 53.89,51.46 ; v1(54.01,51.58) 54.13,51.46 ; C100.2 v3(26.03,23.84) ; C100.2 26.61,24.29 ; C100.2 26.61,23.38 ; 53.09,49.3 v1(53.21,49.18) ; 53.09,49.3 C290.2 52.53,49.3 ; 53.09,49.3 53.33,49.3 ; v1(53.21,49.18) 53.33,49.3 ; v1(53.21,49.18) 53.4,48.99 ; 93.64,55.39 v1(93.85,54.75) 93.64,54.12 ; C312.2 55.84,6.15 ; C312.2 55.84,4.44 ; C312.2 56.64,5.29 ; 49.72,47.29 C199.2 ; 53.36,54.63 53.07,54.63 ; 53.36,54.63 v1(53.21,54.78) 53.07,54.63 ; v1(49.61,45.58) v1(48.81,45.58) ; 52.9,45.66 C298.2 52.9,46.3 ; 52.9,45.66 v1(52.81,45.58) 52.9,45.5 ; 52.9,45.66 52.9,45.5 ; v1(50.01,51.58) 49.89,51.46 ; v1(50.01,51.58) v1(50.01,52.38) ; v1(50.01,51.58) 50.13,51.46 ; 49.89,51.46 50.13,51.46 ; 49.89,51.46 C281.2 49.33,51.46 ; C133.2 56.78,24.47 ; 56.93,44.28 C271.2 ; C271.2 57.34,43.83 ; C271.2 57.34,44.65 ; 37.97,4.87 C66.1 ; C66.1 38.53,5.43 ; C66.1 37.41,5.43 ; 53.33,49.3 C268.2 53.4,49.11 53.4,48.99 ; P1.G11 v1(90.9,47.13) ; 99.37,45.23 P1.A12 v1(98.52,44.59) P1.A13 ; v1(53.21,52.38) v1(53.21,51.58) ; v1(53.21,52.38) 53.5,52.38 ; v1(53.21,52.38) 52.93,52.38 ; v1(52.41,49.18) 52.27,49.18 52.07,48.98 ; v1(52.41,49.18) 52.29,49.3 ; v1(52.41,49.18) 52.53,49.3 ; 54.17,22.03 54.17,21.29 ; R2.1 76.31,28.08 ; R2.1 76.87,27.52 ; R2.1 76.31,26.96 ; v1(48.41,48.78) 48.4,48.79 C306.2 ; v1(50.01,52.38) 49.92,52.47 C257.2 49.33,52.47 ; 36.78,5.04 v1(35.31,5.04) 33.83,5.04 ; 54.17,20.4 C123.2 ; 54.17,20.4 v2(54.22,20.34) ; v2(56.77,16.22) 56.77,16.03 56.9,15.9 C130.2 ; P1.J8 v1(88.77,50.94) ; C131.2 54.17,21.29 ; C131.2 53.76,21.17 ; 54.17,21.29 v2(54.22,21.34) ; R102.2 54.55,46.32 54.55,46.25 ; 97.45,32.53 v1(97.66,31.89) 97.45,31.26 ; C315.2 45.43,35.14 ; C315.2 45.02,34.68 ; C315.2 45.02,35.6 ; 26.85,33.62 R12.2 ; R12.2 27.3,33.21 ; R12.2 27.76,33.62 ; C121.2 57.72,23.28 ; C121.2 57.72,22.36 ; C121.2 58.13,22.82 ; P1.B18 v1(97.66,36.97) 97.45,36.34 ; C326.2 40.6,30.54 ; C326.2 40.2,30.08 ; 94.91,13.48 v1(94.3,13.78) ; 53.89,51.46 54.13,51.46 ; v1(55.21,50.38) 55.21,50.86 ; v1(55.21,50.38) 55.75,50.38 ; v1(55.21,50.38) 55.05,50.22 C258.2 ; P1.B6 v1(97.66,52.21) P1.B7 ; 52.26,51.46 52.38,51.58 v1(52.41,51.58) ; 52.26,51.46 C293.2 51.73,51.46 ; 52.26,51.46 52.53,51.46 ; 34.92,29.61 C25.2 34.26,30.31 ; C291.2 50.74,49.1 v1(50.81,49.18) 50.93,49.3 C198.2 51.49,49.3 v1(51.61,49.18) 51.73,49.3 C200.2 ; C300.2 51.12,56.04 ; C300.2 51.52,55.59 ; C300.2 51.12,55.27 v1(51.21,55.18) 51.18,55.15 C303.2 51.49,54.63 ; 75.48,10.1 U6.12 76.23,10.51 ; C294.2 49.72,54.49 ; 49.72,54.49 49.72,54.27 ; 49.72,54.49 v1(49.61,54.38) 49.72,54.27 ; 59.02,50.04 R104.2 ; R104.2 59.02,51.74 ; R104.2 59.82,50.89 ; 50.33,15.07 C49.1 49.77,14.51 ; 54.55,46.25 C266.2 54.55,45.71 ; 54.55,46.25 v1(54.41,46.38) ; 51.97,52.38 v1(51.61,52.38) ; U2.10 76.2,35.35 ; R73.2 27.3,37.83 ; R73.2 27.76,37.43 ; R73.2 26.85,37.43 ; 97.45,26.18 v3(98.08,25.56) ; 64,36.84 C245.1 64.55,36.28 ; 33.83,25.93 R96.2 ; R96.2 34.75,25.93 ; R96.2 34.29,26.34 ; U2.11 76.7,35.35 ; v3(47.62,60.29) 47.56,60.35 C333.2 ; 52.9,45.5 C301.2 ; 43.17,39.91 R94.2 43.73,40.47 ; R44.2 35.85,22.06 ; 76.23,7.19 U6.7 ; v1(52.41,51.58) 52.53,51.46 ; v3(99.49,38.88) 99.79,38.57 v1(99.79,36.97) 99.79,35.44 99.42,35.07 P1.A20 v1(98.52,34.43) P1.A21 99.51,33.8 99.79,33.52 v1(99.79,31.89) 99.79,30.15 v3(99.57,29.93) ; P1.H9 v1(90.04,48.4) ; v1(90.04,52.21) P1.H6 ; 65.66,16.41 C24.2 66.32,15.71 ; 49.72,54.27 C279.2 ; C13.2 44.01,29.09 ; C13.2 43.36,28.44 ; C13.2 43.97,28.48 ; 58.06,19.77 C111.2 57.66,19.31 ; C123.2 54.17,19.4 v2(54.22,19.34) ; C123.2 53.76,19.65 ; 52.53,49.3 52.29,49.3 ; v1(55.21,54.38) 55.53,54.06 R109.1 ; 51.49,51.46 v1(51.61,51.58) ; 51.49,51.46 51.73,51.46 ; v1(51.61,51.58) v1(51.61,52.38) ; v1(51.61,51.58) 51.73,51.46 ; 54.13,51.46 C302.2 54.81,51.46 ; 38.06,12.28 U28.7 ; 53.21,22.73 C137.2 53.67,23.14 ; 57.34,44.65 57.34,44.74 ; 57.34,44.65 v1(57.21,44.78) ; 66.51,15.58 C28.2 67.07,16.14 ; 37.64,29.23 C4.2 37.08,28.67 ; v1(37.08,36.54) 36.85,36.77 U18.31 ; C269.2 54.55,45.45 ; 54.55,45.45 v1(54.41,45.58) 54.55,45.71 ; 54.55,45.45 54.55,45.71 ; v1(48.81,47.18) 48.81,47.44 C272.2 48.89,47.11 ; 43.87,39.47 C314.2 ; C314.2 44.32,39.88 ; C314.2 44.78,39.47 ; v1(48.01,46.38) 48.13,46.5 C275.2 ; C196.2 58.74,54.3 v1(58.81,54.38) ; C196.2 58.74,53.35 ; C196.2 59.14,53.81 ; v1(49.21,49.58) 49.05,49.58 C308.2 ; U5.10 65.91,11.13 v1(65.66,10.88) ; 46.41,60.35 C333.2 ; C333.2 46.86,59.94 ; U2.4 72.89,32.85 v3(72.77,32.73) ; C200.2 52.07,48.98 ; C200.2 52.29,49.3 ; 87.29,14.75 v3(87.93,14.11) ; C275.2 47.68,47.01 ; C275.2 48.59,47.01 ; 43.17,42.05 C336.2 43.73,41.49 ; 56.07,53.6 R109.1 ; R109.1 56.07,54.52 ; 55.24,54.54 C105.2 55.7,54.95 ; C15.2 v3(32,34.25) ; C15.2 32.58,33.79 ; C15.2 32.58,34.71 ; v3(99.49,40.15) 99.79,40.45 v1(99.79,42.05) 99.79,43.65 v3(99.49,43.96) ; 51.49,54.63 51.61,54.76 v1(51.61,54.78) 51.76,54.63 ; 51.49,54.63 51.76,54.63 ; P1.C32 v1(96.39,19.19) P1.C33 ; 34.16,32.31 C328.2 33.6,32.87 ; 55.49,3.08 C339.2 ; C339.2 56.05,3.64 ; C339.2 55.49,4.2 ; 81.65,65.31 R114.2 82.21,65.87 ; v3(99.36,56.02) 99.79,56.46 v1(99.79,57.29) 99.79,58.72 99.31,59.2 P1.A1 ; 55.44,48.78 R110.1 55.84,49.24 ; 70.74,29.68 C35.2 71.31,29.22 ; 92.37,14.75 v3(93.01,14.11) ; 97.45,21.1 v3(98.1,20.45) ; 41.31,39.46 C75.2 40.75,38.9 ; 52.9,46.3 v1(52.81,46.38) 52.9,46.46 ; 52.9,46.3 52.9,46.46 ; v1(37.59,34.5) 37.85,34.25 U18.21 ; 53.85,55.92 C141.2 53.44,55.46 ; 49.69,23.84 C135.2 50.1,24.29 ; 75.48,9.1 U6.10 77.47,9.1 v1(77.72,8.85) ; 76.58,10.85 U6.13 ; C295.2 52.9,46.46 ; 71.01,31.91 C31.2 ; v1(37.08,40.09) 37.21,39.97 C16.2 37.91,40.14 C17.2 37.91,41.43 v3(37.72,41.62) ; P1.C17 v1(96.39,39.51) P1.C16 ; 49.67,24.42 C93.2 49.11,24.98 ; 52.07,48.98 C286.2 ; P1.J11 v1(88.77,47.13) ; 77.6,34.65 U2.12 77.2,35.35 ; 41.91,31.04 C330.2 42.47,31.6 ; 97.45,17.29 v1(97.66,16.65) 97.45,16.02 ; 97.45,27.45 v1(96.93,27.45) ; 35.85,17.49 R49.2 35.29,16.93 ; C282.2 53.4,48.99 ; C116.2 52.64,18.51 ; P1.A16 v1(98.52,39.51) P1.A17 ; P1.A37 v1(98.52,14.11) P1.A36 ; 92.37,52.85 v1(92.17,52.21) ; C44.1 57.38,18.55 ; C197.2 48.24,51.02 ; 56.83,51.96 v1(56.81,51.98) ; U7.4 36.46,6.49 ; P1.G8 v1(90.9,50.94) ; 22.92,64.73 C73.2 22.22,64.07 ; 35.51,29.23 C81.2 36.07,28.67 ; 54.48,24.81 C132.2 54.03,24.41 ; R79.1 55.54,48.22 ; P1.E38 v1(93.01,11.57) ; C46.2 69.08,12.08
  BOTTOM w0.381: U27.6 63.44,29.42
  BOTTOM w0.406: P1.G23 v3(91.74,31.89) ; C335.2 56.53,14.87 ; C335.2 55.97,14.31 ; C335.2 56.53,13.75 ; v3(91.69,43.27) 91.12,42.69 P1.G14 ; P1.J23 v3(89.2,31.89) ; 87.29,33.8 v3(87.93,34.43) P1.J20 v3(89.2,34.43) 89.83,33.8 v3(90.47,34.43) P1.G20 v3(91.74,34.43) 92.37,33.8 v3(93.01,34.43) P1.E20 ; 94.91,36.34 v3(94.28,36.97) ; 87.29,41.42 v3(87.93,40.78) ; v3(93.01,39.51) P1.E17 v3(94.28,39.51) 94.91,40.15 ; 54.62,24.93 C340.2 ; C340.2 54.06,25.49 ; C340.2 54.62,26.05 ; P1.E35 v1(93.01,16.65) ; P1.G17 v3(91.69,39.46) ; P1.G35 v1(90.47,16.65) ; v3(91.81,41.98) 92.37,41.42 v3(93.01,42.05) P1.E14 v3(95.55,44.59) ; P1.J35 v1(89.2,16.65) ; P1.J17 v3(88,39.44) ; P1.C38 v1(95.55,11.57) 94.91,10.94 ; P1.H15 v3(89.2,40.78) ; 87.29,37.61 v3(87.93,36.97) ; P1.A4 v3(99.36,56.02) ; 92.37,37.61 v3(91.74,36.97) ; P1.H18 v3(89.2,36.97) ; P1.J5 v6(89.2,54.75) P1.J4 v6(87.93,54.75) P1.J5 ; 91.1,54.12 v6(91.74,54.75) 91.1,55.39 v6(90.47,54.75) 91.1,54.12
  BOTTOM w0.508: 81.46,4.42 C59.1 80.9,3.86 ; 69.47,23.54 C70.2 ; C70.2 70.03,24.1 ; C70.2 68.91,24.1 ; 75.13,3.91 C60.2 ; 94.91,24.91 v3(94.28,24.27) P1.E29 ; v3(99.57,29.93) 99.51,29.99 P1.A24 v3(98.09,29.35) P1.A25 99.36,28.72 ; 94.91,32.53 v1(94.28,31.89) P1.E23 ; P1.C28 v3(95.55,24.27) ; C327.2 v3(41.15,31.51) 41.24,31.6 C330.2 ; 73.72,8.76 C72.1 73.72,6.65 ; v3(86.23,58.51) 86.23,58.13 86.43,57.93 P1.K2 ; 93.64,59.2 v6(93.01,58.56) 92.37,57.93 v3(91.74,58.56) 91.1,59.2 v3(90.47,58.56) P1.H2 v3(89.2,58.56) P1.J1 ; 92.37,22.37 v3(91.64,23.1) P1.G29 v3(90.57,23.11) 89.83,22.37 v3(89.09,23.11) P1.J29 v3(88.03,23.11) 87.29,22.37 ; 87.29,29.99 v3(87.93,29.35) ; Y1.3 22.1,36.66 ; Y1.3 19.81,36.66 ; Y1.3 20.95,37.9 ; 73.85,2.88 C64.2 ; C64.2 74.55,2.22 ; C64.2 74.55,3.54 ; 87.29,18.56 v1(87.93,19.19) P1.J32 v1(89.2,19.19) 89.83,18.56 v1(90.47,19.19) P1.G32 v1(91.74,19.19) 92.37,18.56 v1(93.01,19.19) P1.E32 ; 73.72,9.45 C69.1 ; C69.1 73.72,11.56 ; C69.1 74.63,10.5 ; C91.2 57.26,29.6 ; C91.2 57.82,29.04 ; C91.2 57.26,28.48 ; v3(49.78,15.84) 49.77,15.82 C49.1 ; P1.J38 v3(89.2,11.57) 89.83,10.94 ; P1.D2 v3(95.55,58.56) P1.C1 ; 99.36,14.62 99.23,14.75 P1.A36 ; C236.2 62.5,55.38 ; C236.2 61.94,54.82 ; C236.2 62.5,54.26 ; 60.82,17.18 C122.2 ; C122.2 60.82,18.3 ; C122.2 61.38,17.74 ; v3(93.01,9.03) 93.39,9.03 93.64,9.29 P1.E40 ; C96.2 34.96,14.69 ; C96.2 34.4,15.25 ; C96.2 34.4,14.13 ; 74.33,13.1 C62.1 73.28,12.2 ; v3(93.01,29.35) 92.37,29.99 ; T2.3 13.72,42.7 ; T2.3 13.08,41.74 ; T2.3 13.72,40.79 ; v3(81.83,33.42) 80.78,33.42 C23.1 ; P1.A33 99.36,18.56 ; 82.55,5.42 C58.1 83.4,6.22 ; 92.37,10.94 v3(91.74,11.57) P1.G38 ; P1.E8 v3(94.28,49.67) ; P1.A40 98.72,9.01 ; P1.C9 v3(95.55,49.67) P1.C8 ; 68.62,29.08 C37.2 ; C37.2 69.47,28.28 ; C37.2 70.32,29.08 ; v3(24,60.16) 25.18,60.16 R3.1 ; 71.12,27.65 C26.2 ; C26.2 71.92,28.5 ; C26.2 71.92,26.79 ; P1.A32 99.36,19.83 ; v3(87.93,9.03) 88.22,9.03 88.56,9.38 P1.J40 ; P1.A37 v4(99.36,13.48) ; C235.2 62.12,61.23 ; C235.2 61.56,60.67 ; C235.2 62.12,60.11 ; P1.A1 v3(98.09,58.56) ; P1.A29 v3(99.49,23.64) ; C31.2 v3(70.23,32.47) ; 92.37,45.23 v3(93.01,44.59) ; 89.83,29.99 v3(90.47,29.35) ; P1.A9 v3(99.61,49.04) ; C256.2 41.8,48.4 ; C256.2 41.24,47.84 ; C256.2 41.8,47.28 ; P1.A16 v3(99.49,40.15) ; 66.29,23.8 C80.2 ; C80.2 65.73,24.36 ; C80.2 66.85,24.36 ; P1.A28 v3(99.49,24.91) ; P1.E26 v3(93.01,26.81) 92.37,26.18 v3(91.74,26.81) P1.G26 89.83,26.18 v3(89.2,26.81) P1.J26 v3(87.93,26.81) 87.29,26.18 ; P1.J14 v3(87.93,43.32) ; P1.C29 v3(96.82,24.27) ; C238.2 22.15,50.74 ; C238.2 21.6,50.18 ; C238.2 22.15,49.62 ; P1.C25 v3(95.55,29.35) P1.C24 ; R46.2 v3(36.2,19.77) ; P1.A13 v3(99.49,43.96) ; P1.A17 v3(99.49,38.88) ; 79.38,2.12 C55.1 80.23,2.92 ; C77.2 37.46,8.34 ; v3(86.4,52.85) P1.K6 ; C46.2 v3(69.08,10.63) ; P1.A8 v3(99.61,50.31) ; 87.29,10.94 86.67,10.94 ; 94.91,28.72 v3(94.28,29.35) ; P1.C40 96.18,9.07
  BOTTOM w0.635: C86.2 44.67,14.02 ; C86.2 42.96,14.02 ; C86.2 43.81,14.82 ; 57.47,30.12 C82.2 ; C82.2 57.47,31.52 ; C82.2 58.1,30.82 ; C95.2 43.18,8.09 ; C95.2 42.38,7.24 ; C95.2 42.38,8.94 ; 70.99,55.71 C227.2 ; C227.2 71.84,56.51 ; C227.2 70.14,56.51 ; 66.48,30.38 C194.2 ; C194.2 67.18,29.74 ; C194.2 67.88,30.38 ; C313.2 60.64,28.73 ; C313.2 59.94,29.36 ; C313.2 59.24,28.73 ; 38.52,47.55 C249.2 ; C249.2 39.37,48.35 ; C249.2 40.22,47.55 ; C77.2 36.54,9.19 ; 41.66,55.13 U19.8 ; U19.8 41.1,56.08 ; U19.8 41.66,57.03 ; 62.65,16.05 R17.1 63.5,16.85 ; 41.44,46.79 C253.2 40.64,45.93 ; C230.2 61.89,59.61 ; C230.2 61.09,58.76 ; C230.2 61.89,57.91 ; C341.2 43.18,15.96 ; C341.2 42.38,15.11 ; C341.2 42.38,16.81 ; 21.67,47.3 C233.2 ; C233.2 20.87,48.15 ; C233.2 21.67,49 ; C241.2 60.01,30.5 ; C241.2 59.31,29.87 ; C241.2 58.61,30.5 ; 48.01,26.63 C84.2 ; C84.2 48.81,25.78 ; C84.2 48.81,27.48 ; 61.89,55.88 C231.2 ; C231.2 61.89,57.58 ; C231.2 61.09,56.73 ; C87.2 35.56,12.79 ; C87.2 34.76,13.64 ; C87.2 34.76,11.94 ; C68.2 32.38,9.23 ; C68.2 33.24,8.43 ; C68.2 31.53,8.43 ; 31.53,4.37 C63.2 ; C63.2 32.38,5.17 ; C63.2 33.24,4.37 ; 63.18,27.58 C195.2 ; C195.2 63.82,28.28 ; C195.2 63.18,28.98 ; 57.59,33.55 C85.2 ; C85.2 57.59,34.95 ; C85.2 56.96,34.25 ; 32.22,47.93 C244.2 31.37,48.73
  BOTTOM w0.762: 61.18,14.73 C106.2 ; C106.2 61.18,16.43 ; C106.2 61.98,15.58 ; 64.69,7.07 C27.1 65.6,6.02 ; 63.25,6.06 L1.1 64.01,7.2 ; 83.44,33.4 C163.2 84.7,32.35 ; 81.12,14.78 C57.1 80.26,15.58 ; C51.1 81.52,36.41 ; C51.1 80.26,35.35 ; C51.1 79.01,36.41 ; 82.18,23.33 C161.2 ; C161.2 83.44,22.27 ; C161.2 84.7,23.33 ; 63.56,5.46 C48.1 ; C48.1 63.56,3.35 ; C48.1 64.47,4.41 ; 79.34,33.81 C23.1 ; C23.1 80.39,34.71 ; C23.1 81.45,33.81 ; 61.18,12.44 C311.2 ; C311.2 61.18,14.15 ; C311.2 61.98,13.3 ; 83.06,13.63 C56.1 84.11,12.72 ; 63.56,1.19 C52.1 ; C52.1 64.47,2.25 ; C52.1 63.56,3.3 ; 76.01,35.99 C42.1 76.91,37.04 ; 66.8,66.13 C205.2 ; C205.2 67.6,66.98 ; C205.2 67.6,65.28 ; 63.12,23.58 C88.2 62.32,22.73
  BOTTOM w1.016: 2.54,53.36 J6.4 ; J6.4 5.33,54.89 ; J6.4 2.54,56.41 ; 2.54,27.96 J4.4 ; J4.4 5.33,29.49 ; J4.4 2.54,31.01 ; 2.54,44.85 J6.2 ; J6.2 5.33,46.38 ; J6.2 2.54,47.9 ; J4.2 2.54,22.5 ; J4.2 5.33,20.98 ; J4.2 2.54,19.45
  vias: v1(3.17,26.63) v1(3.17,23.84) v1(3.3,52.03) v1(3.3,49.24) v1(3.68,26.63) v1(3.68,23.84) v1(3.81,52.03) v1(3.81,49.24) v1(4.19,26.63) v1(4.19,23.84) v1(4.32,52.03) v1(4.32,49.24) v1(4.7,26.63) v1(4.7,23.84) v1(4.83,52.03) v1(4.83,49.24) v1(5.21,26.63) v1(5.21,23.84) v1(5.33,52.03) v1(5.33,49.24) v1(5.72,26.63) v1(5.72,23.84) v1(5.84,52.03) v1(5.84,49.24) v1(6.22,26.63) v1(6.22,23.84) v1(6.35,52.03) v1(6.35,49.24) v1(6.73,26.63) v1(6.73,23.84) v1(6.86,52.03) v1(6.86,49.24) v1(6.98,15.33) v1(6.98,14.82) v1(6.98,14.31) v1(6.98,13.8) v1(6.98,13.3) v1(7.24,26.63) v1(7.24,23.84) v1(7.37,52.03) v1(7.37,49.24) v1(7.49,15.33) v1(7.49,14.82) v1(7.49,13.8) v1(7.49,13.3) v1(7.75,26.63) v1(7.75,23.84) v1(7.87,52.03) v1(7.87,49.24) v1(8,15.33) v1(8,14.82) v1(8,14.31) v1(8,13.8) v1(8,13.3) v1(8.25,26.63) v1(8.25,23.84) v1(8.38,52.03) v1(8.38,49.24) v1(8.76,26.63) v1(8.76,23.84) v1(8.89,52.03) v1(8.89,49.24) v1(9.27,26.63) v1(9.27,23.84) v1(9.4,52.03) v1(9.4,49.24) v1(9.78,26.63) v1(9.78,23.84) v1(9.91,52.03) v1(9.91,49.24) v1(10.29,26.63) v1(10.29,23.84) v1(10.41,52.03) v1(10.41,49.24) v1(10.8,23.84) v1(10.92,52.03) v1(10.92,49.24) v1(11.05,26.63) v1(11.3,23.84) v1(11.43,52.03) v1(11.43,49.24) v1(11.56,26.63) v1(11.81,23.84) v1(11.94,52.03) v1(11.94,49.24) v1(12.06,26.63) v1(12.32,23.84) v1(12.45,52.03) v1(12.45,49.24) v1(12.57,26.63) v1(12.83,23.84) v1(12.95,52.03) v1(12.95,49.24) v1(13.08,26.63) v1(13.33,23.84) v1(13.46,52.03) v1(13.46,49.24) v1(13.59,26.63) v1(13.84,23.84) v1(13.97,52.03) v1(13.97,49.24) v1(14.1,26.63) v1(14.35,23.84) v1(14.48,52.03) v1(14.48,49.24) v1(14.61,26.63) v1(14.99,52.03) v1(14.99,49.24) v1(14.99,23.84) v1(15.11,26.63) v1(15.49,52.03) v1(15.49,49.24) v1(15.49,23.84) v1(16,52.03) v1(16,49.24) v1(16.51,52.03) v1(16.51,49.24) v1(17.02,52.03) v1(17.02,49.24) v1(17.53,52.03) v1(17.53,49.24) v1(17.65,26.63) v1(17.65,23.84) v1(18.03,20.92) v1(18.03,20.41) v1(18.03,19.9) v1(18.03,19.39) v1(18.16,26.5) v1(18.54,20.41) v1(18.54,19.9) v1(18.54,19.39) v1(18.67,26.38) v1(19.05,52.03) v1(19.05,49.24) v1(19.05,21.42) v1(19.05,20.92) v1(19.05,19.9) v1(19.05,19.39) v1(19.05,18.88) v1(19.18,26.12) v1(19.56,52.03) v1(19.56,49.24) v1(19.56,25.74) v1(19.56,20.92) v1(19.56,20.41) v1(19.56,19.39) v1(19.94,25.36) v1(20.07,52.03) v1(20.07,49.24) v1(20.07,20.41) v1(20.07,19.9) v1(20.19,24.85) v1(20.32,24.22) v1(20.57,49.24) v1(21.08,49.24) v1(21.59,52.03) v1(21.59,49.24) v1(22.99,65.37) v1(22.99,64.86) v1(22.99,64.35) v1(22.99,63.84) v1(22.99,63.33) v1(23.37,16.6) v1(23.5,65.37) v1(23.5,63.84) v1(23.5,63.33) v1(24,65.37) v1(24,64.35) v1(24,63.84) v1(24,63.33) v1(25.12,19.72) v1(25.12,19.21) v1(25.12,18.71) v1(25.12,18.2) v1(25.12,17.69) v1(25.12,17.18) v1(25.12,16.67) v1(25.12,16.17) v1(25.12,15.66) v1(25.12,15.15) v1(25.12,14.64) v1(25.12,14.13) v1(25.12,13.63) v1(25.12,13.12) v1(25.12,12.61) v1(25.12,12.1) v1(25.12,11.59) v1(26.03,42.12) v1(26.03,41.62) v1(26.03,41.11) v1(26.03,40.6) v1(26.03,40.09) v1(26.03,29.04) v1(26.03,28.54) v1(26.03,28.03) v1(26.54,42.12) v1(26.54,41.62) v1(26.54,40.6) v1(26.54,40.09) v1(26.54,29.55) v1(26.54,28.54) v1(26.54,28.03) v1(27.05,42.12) v1(27.05,41.11) v1(27.05,40.6) v1(27.05,40.09) v1(27.05,29.55) v1(27.05,29.04) v1(27.05,28.54) v1(27.05,28.03) v1(27.97,19.77) v1(27.97,19.26) v1(27.97,18.76) v1(27.97,18.25) v1(27.97,17.74) v1(27.97,17.23) v1(27.97,16.72) v1(27.97,16.22) v1(27.97,15.71) v1(27.97,15.2) v1(27.97,14.69) v1(27.97,14.18) v1(27.97,13.68) v1(27.97,13.17) v1(27.97,12.66) v1(27.97,12.15) v1(27.97,11.64) v1(28.07,51.9) v1(28.07,50.89) v1(28.58,51.9) v1(28.58,51.4) v1(28.58,50.89) v1(29.08,51.9) v1(29.08,51.4) v1(29.08,50.89) v1(29.59,51.9) v1(29.59,51.4) v1(29.59,50.89) v1(30.1,51.9) v1(30.1,50.89) v1(33.53,25.61) v1(33.91,63.08) v1(33.91,62.57) v1(33.91,62.06) v1(34.29,5.55) v1(34.29,5.04) v1(34.29,4.53) v1(34.42,63.08) v1(34.42,62.57) v1(34.42,62.06) v1(34.67,46.7) v1(34.67,46.19) v1(34.67,45.68) v1(34.67,45.17) v1(34.8,5.55) v1(34.8,5.04) v1(34.8,4.53) v1(34.92,63.08) v1(34.92,62.06) v1(35.18,46.19) v1(35.18,45.68) v1(35.18,45.17) v1(35.31,5.55) v1(35.31,4.53) v1(35.43,63.08) v1(35.43,62.57) v1(35.43,62.06) v1(35.69,46.7) v1(35.69,46.19) v1(35.69,45.68) v1(35.69,45.17) v1(35.81,5.04) v1(35.81,4.53) v1(35.94,63.08) v1(35.94,62.57) v1(35.94,62.06) v1(36.2,46.7) v1(36.2,46.19) v1(36.2,45.68) v1(36.2,45.17) v1(36.32,5.55) v1(36.32,5.04) v1(36.32,4.53) v1(36.58,37.04) v1(36.58,36.54) v1(36.58,36.03) v1(36.58,35.52) v1(36.58,35.01) v1(36.58,34.5) v1(36.58,34) v1(37.08,37.04) v1(37.08,36.03) v1(37.08,35.52) v1(37.08,35.01) v1(37.08,34.5) v1(37.08,34) v1(37.59,37.04) v1(37.59,36.54) v1(37.59,36.03) v1(37.59,35.52) v1(37.59,35.01) v1(37.59,34) v1(38.1,37.04) v1(38.1,36.54) v1(38.1,36.03) v1(38.1,35.52) v1(38.1,35.01) v1(38.1,34.5) v1(38.1,34) v1(38.61,37.04) v1(38.61,36.54) v1(38.61,36.03) v1(38.61,35.52) v1(38.61,35.01) v1(38.61,34.5) v1(38.61,34) v1(39.12,37.04) v1(39.12,36.54) v1(39.12,36.03) v1(39.12,35.52) v1(39.12,34) v1(39.62,36.54) v1(39.62,36.03) v1(39.62,35.52) v1(39.62,35.01) v1(39.62,34.5) v1(39.62,34) v1(42.29,59.9) v1(42.29,59.4) v1(42.29,58.89) v1(42.29,58.38) v1(42.29,57.87) v1(42.62,38.95) v1(42.8,59.9) v1(42.8,59.4) v1(42.8,58.89) v1(42.8,58.38) v1(42.8,57.87) v1(43.31,59.9) v1(43.31,59.4) v1(43.31,58.89) v1(43.31,58.38) v1(43.31,57.87) v1(43.81,59.9) v1(43.81,59.4) v1(43.81,58.89) v1(43.81,58.38) v1(43.81,57.87) v1(44.32,59.9) v1(44.32,59.4) v1(44.32,58.89) v1(44.32,58.38) v1(44.32,57.87) v1(44.83,59.9) v1(44.83,59.4) v1(44.83,58.89) v1(44.83,58.38) v1(44.83,57.87) v1(48.01,45.58) v1(52.04,27.04) v1(53.21,25.87) v1(53.38,24.65) v1(53.59,28.54) v1(54.74,27.39) v1(62.26,32.95) v1(62.26,32.52) v1(62.26,32.09) v1(62.26,31.66) v1(62.26,31.23) v1(62.69,32.95) v1(62.69,32.52) v1(62.69,32.09) v1(62.69,31.66) v1(62.69,31.23) v1(63.12,32.95) v1(63.12,32.52) v1(63.12,32.09) v1(63.12,31.66) v1(63.12,31.23) v1(63.55,32.95) v1(63.55,32.52) v1(63.55,32.09) v1(63.55,31.66) v1(63.98,32.95) v1(63.98,32.52) v1(63.98,32.09) v1(63.98,31.66) v1(63.98,31.23) v1(64.64,11.39) v1(65.02,37.17) v1(65.02,36.66) v1(65.02,36.16) v1(65.15,11.39) v1(65.15,10.88) v1(65.15,10.37) v1(65.53,37.17) v1(65.53,36.66) v1(65.53,36.16) v1(65.66,11.39) v1(65.66,10.37) v1(66.04,37.17) v1(66.04,36.66) v1(66.04,36.16) v1(66.04,35.65) v1(71.5,63.08) v1(71.5,62.57) v1(71.5,62.06) v1(71.5,61.56) v1(72.01,63.08) v1(72.01,62.57) v1(72.01,62.06) v1(72.01,61.56) v1(72.52,63.08) v1(72.52,62.57) v1(72.52,62.06) v1(72.52,61.56) v1(73.03,63.08) v1(73.03,62.06) v1(73.03,61.56) v1(74.93,31.96) v1(74.93,31.46) v1(75.44,32.47) v1(75.44,31.96) v1(75.44,31.46) v1(75.87,56.63) v1(75.87,54.8) v1(75.95,32.47) v1(75.95,31.96) v1(75.95,31.46) v1(76.45,32.47) v1(76.45,31.96) v1(76.45,31.46) v1(76.96,32.47) v1(76.96,31.96) v1(76.96,31.46) v1(77.22,9.36) v1(77.22,8.85) v1(77.22,8.34) v1(77.5,56.58) v1(77.72,9.87) v1(77.72,8.34) v1(77.72,7.83) v1(78,58.02) v1(78,57.21) v1(78.23,9.87) v1(78.23,9.36) v1(78.23,8.85) v1(78.23,8.34) v1(78.23,7.83) v1(78.51,58.66) v1(78.74,9.87) v1(78.74,9.36) v1(78.74,8.85) v1(78.74,8.34) v1(78.74,7.83) v1(79.25,9.87) v1(79.25,9.36) v1(79.25,8.85) v1(79.25,8.34) v1(79.25,7.83) v1(81,52.79) v1(81,50.73) v1(82.59,50.94) v1(82.93,64.35) v1(82.93,63.59) v1(82.93,62.83) v1(83.49,33.56) v1(83.57,37.17) v1(83.57,36.03) v1(83.57,34.89) v1(83.69,63.59) v1(83.69,62.83) v1(84.45,64.35) v1(84.45,63.59) v1(84.45,62.83) v1(85.47,37.17) v1(85.9,34.63) v1(85.93,32.07) v1(86.02,50.7) v1(86.02,48.26) v1(93.9,47.13) v1(99.79,47.13) v1(100.34,27.17) v1(100.34,26.46) v1(100.34,22.08) v1(100.34,21.36) v1(103.76,14.06) v1(103.76,13.55) v1(103.76,13.04) v1(103.76,12.53) v1(104.27,14.06) v1(104.27,13.55) v1(104.27,13.04) v1(104.27,12.53) v1(104.78,14.06) v1(104.78,13.55) v1(104.78,13.04) v1(104.78,12.53) v1(105.28,14.06) v1(105.28,13.55) v1(105.28,13.04) v1(105.28,12.53) v2(55.22,23.34) v3(1.91,17.61) v3(1.91,14.06) v3(2.2,66.82) v3(2.2,57.93) v3(2.67,15.54) v3(3.05,35.39) v3(3.17,27.39) v3(3.43,1.61) v3(3.68,52.54) v3(3.81,16.6) v3(3.94,41.74) v3(4.06,48.73) v3(4.57,52.54) v3(4.74,60.47) v3(4.7,27.39) v3(4.83,48.73) v3(5.08,32.22) v3(5.46,52.54) v3(5.46,48.73) v3(6.22,27.39) v3(6.73,30.69) v3(7.11,52.54) v3(7.11,48.73) v3(7.28,57.93) v3(7.62,27.39) v3(7.87,17.74) v3(8.13,19.9) v3(8.25,6.95) v3(8.38,45.81) v3(8.38,35.65) v3(8.38,30.31) v3(8.51,40.35) v3(9.27,27.39) v3(9.65,45.93) v3(9.65,40.6) v3(9.65,30.19) v3(9.82,66.82) v3(9.82,60.47) v3(9.82,55.39) v3(9.78,34.76) v3(9.91,16.34) v3(9.91,15.58) v3(10.67,16.72) v3(10.8,48.73) v3(10.92,23.33) v3(11.43,16.72) v3(11.68,52.54) v3(11.81,27.14) v3(12.19,19.01) v3(12.36,64.28) v3(12.36,57.93) v3(12.7,47.46) v3(12.7,45.92) v3(12.7,40.59) v3(12.7,38.82) v3(12.7,37.43) v3(12.7,35.51) v3(12.7,28.66) v3(13.84,23.2) v3(14.22,48.73) v3(14.29,6.95) v3(14.73,60.16) v3(14.9,66.82) v3(14.86,27.14) v3(15.24,12.41) v3(15.62,45.93) v3(15.62,40.6) v3(15.62,34.76) v3(15.62,30.19) v3(15.75,52.67) v3(16,47.97) v3(16,12.41) v3(16.38,61.56) v3(16.76,12.41) v3(17.02,62.95) v3(17.02,45.81) v3(17.19,30.17) v3(17.53,39.97) v3(17.91,61.56) v3(17.91,60.16) v3(18.8,45.43) v3(18.92,27.01) v3(19.18,12.53) v3(19.3,38.82) v3(19.43,61.56) v3(19.37,6.95) v3(19.69,46.44) v3(19.81,48.73) v3(19.94,28.54) v3(19.98,54.12) v3(20.45,25.87) v3(20.45,12.28) v3(20.57,47.59) v3(20.62,38.88) v3(20.83,62.95) v3(20.95,61.56) v3(20.95,60.16) v3(21.25,47.01) v3(21.25,38.88) v3(21.51,42.18) v3(22.02,26.64) v3(22.22,6.95) v3(22.22,6.18) v3(22.48,61.56) v3(22.73,43.39) v3(23.75,10.76) v3(23.76,7.58) v3(24,61.56) v3(24,11.77) v3(24.56,39.13) v3(24.56,38.37) v3(24.64,26.5) v3(25.4,43.14) v3(25.95,26.31) v3(26.54,39.46) v3(26.54,3.26) v3(27.05,48.6) v3(26.97,26.31) v3(27.6,55.39) v3(27.69,47.59) v3(27.69,46.7) v3(27.81,32.73) v3(27.86,26.31) v3(27.88,39.08) v3(28.49,45.99) v3(28.49,44.85) v3(28.49,43.96) v3(28.58,23.33) v3(28.58,11.77) v3(28.7,32.73) v3(28.72,26.28) v3(28.7,19.52) v3(29.21,3.14) v3(29.34,10.76) v3(29.34,4.41) v3(29.38,47.13) v3(30.14,55.39) v3(30.23,23.07) v3(30.23,21.8) v3(30.23,20.92) v3(30.23,19.52) v3(30.73,9.23) v3(30.73,7.45) v3(31.11,26.28) v3(31.24,43.14) v3(31.16,8.4) v3(31.29,4.33) v3(31.54,37.99) v3(31.54,37.23) v3(31.5,19.52) v3(31.75,16.22) v3(32.3,5.48) v3(32.51,66.13) v3(32.68,55.39) v3(33.45,4.33) v3(33.53,67.27) v3(33.53,64.98) v3(33.57,8.4) v3(34.16,30.95) v3(34.92,13.93) v3(34.92,11.64) v3(35.05,54.32) v3(35.22,29.35) v3(35.18,26.63) v3(35.69,13.93) v3(35.69,11.64) v3(36.07,28.36) v3(36.2,17.49) v3(36.83,63.71) v3(37.08,28.36) v3(37.08,5.93) v3(37.13,1.29) v3(37.34,15.33) v3(37.46,60.29) v3(37.46,58) v3(37.72,8.85) v3(37.72,8.09) v3(37.85,23.58) v3(37.89,2.05) v3(37.97,64.86) v3(37.97,62.57) v3(37.97,61.81) v3(38.1,19.26) v3(38.23,47.59) v3(38.61,59.14) v3(38.73,61.05) v3(38.91,5.86) v3(39.37,48.6) v3(39.37,6.44) v3(39.37,2.88) v3(39.41,1.92) v3(39.75,12.53) v3(39.75,11.52) v3(40.26,12.03) v3(40.51,6.44) v3(40.51,1.99) v3(40.77,47.08) v3(40.84,30.54) v3(40.77,12.53) v3(40.77,11.52) v3(41.57,64.28) v3(41.66,54.95) v3(41.66,47.08) v3(41.78,48.73) v3(42.29,54.06) v3(42.67,14.82) v3(42.67,13.8) v3(42.84,65.55) v3(43.43,15.58) v3(43.56,8.98) v3(43.56,7.82) v3(44.07,41.49) v3(44.07,40.65) v3(44.32,15.58) v3(44.7,27.27) v3(45.21,40.35) v3(45.38,65.55) v3(45.38,63.01) v3(45.47,32.85) v3(45.85,59.65) v3(45.97,40.35) v3(46.1,41.49) v3(46.23,54.06) v3(46.35,33.11) v3(46.48,7.83) v3(46.48,1.99) v3(46.86,31.84) v3(46.99,58) v3(47.12,48.86) v3(47.75,34.89) v3(47.75,33.62) v3(47.75,32.6) v3(47.75,2.88) v3(47.75,1.61) v3(47.92,65.55) v3(47.92,63.01) v3(47.88,7.83) v3(48.51,35.65) v3(48.77,27.77) v3(48.89,32.09) v3(49.15,41.36) v3(50.46,65.55) v3(52.04,65.24) v3(52.58,32.35) v3(52.58,29.3) v3(52.88,40.66) v3(52.88,39.64) v3(53.31,65.24) v3(54.02,42.43) v3(54.02,40.66) v3(55.88,8.34) v3(56.52,63.46) v3(56.52,8.34) v3(56.64,59.52) v3(56.9,33.11) v3(56.9,32.35) v3(57.15,8.34) v3(57.15,5.93) v3(57.15,3.64) v3(57.53,33.11) v3(57.53,32.35) v3(57.58,67.33) v3(57.7,61.67) v3(57.78,3.64) v3(57.91,5.93) v3(58.42,30.44) v3(58.8,67.14) v3(58.93,61.81) v3(59.44,29.55) v3(60.45,30.31) v3(60.71,59.9) v3(60.71,58.63) v3(60.71,56.73) v3(60.83,16.72) v3(61.21,42.38) v3(61.21,40.73) v3(61.21,38.44) v3(61.21,9.61) v3(61.34,5.8) v3(61.47,16.72) v3(61.72,54.82) v3(61.85,67.13) v3(61.85,59.9) v3(61.98,61.8) v3(61.98,5.8) v3(62.1,39.58) v3(62.1,16.72) v3(62.74,40.6) v3(63.16,42.69) v3(63.37,24.09) v3(63.5,5.8) v3(63.88,41.74) v3(63.88,24.09) v3(64.01,28.92) v3(64.39,7.07) v3(64.39,5.8) v3(64.77,67.14) v3(64.77,62.95) v3(64.77,4.53) v3(64.77,3.39) v3(64.77,1.48) v3(65.02,41.74) v3(65.28,37.81) v3(65.28,28.15) v3(65.41,16.72) v3(65.53,24.09) v3(65.7,42.69) v3(65.91,37.81) v3(65.91,5.29) v3(66.17,67.27) v3(66.17,16.72) v3(66.29,61.81) v3(66.29,30.57) v3(66.55,66.13) v3(67.31,24.09) v3(67.69,67.27) v3(67.69,64.98) v3(68.07,16.72) v3(68.2,30.31) v3(68.2,29.55) v3(68.71,24.09) v3(69.72,56.73) v3(70.36,24.09) v3(70.74,28.79) v3(71.92,28.79) v3(72.26,56.73) v3(72.77,29.68) v3(73.15,11.9) v3(73.53,9.1) v3(73.91,11.9) v3(74.17,60.67) v3(74.3,9.1) v3(74.68,3.9) v3(74.68,1.99) v3(74.8,60.67) v3(74.8,59.78) v3(74.8,58.89) v3(74.93,10.88) v3(74.93,10.12) v3(75.06,6.95) v3(75.44,60.67) v3(75.56,58.89) v3(75.82,6.95) v3(76.33,35.65) v3(77.22,36.28) v3(77.22,35.65) v3(77.22,28.15) v3(77.98,36.28) v3(77.98,35.65) v3(79.38,1.74) v3(80.01,16.72) v3(80.64,3.52) v3(81.03,16.72) v3(81.15,59.4) v3(81.15,58.76) v3(81.41,14.18) v3(81.53,24.09) v3(81.83,36.08) v3(81.79,4.15) v3(81.91,59.4) v3(81.91,58.76) v3(82.17,14.18) v3(82.34,37.74) v3(82.55,4.91) v3(83.06,14.18) v3(83.69,6.18) v3(83.95,14.18) v3(84.84,14.18) v3(85.09,24.09) v3(85.09,23.33) v3(85.6,59.14) v3(85.6,58.51) v3(85.85,24.09) v3(85.85,23.33) v3(86.23,59.78) v3(86.23,59.14) v3(86.66,11.57) v3(86.68,1.23) v3(88.9,60.16) v3(95.55,9.03) v3(98.09,9.03) v3(99.49,45.23) v3(100.9,20.15) v3(101.9,31.69) v3(101.87,29.94) v3(103.14,56.09) v3(103.14,49.36) v3(103.14,42.51) v3(104.01,50.51) v3(104.14,36.28) v3(105.02,42.51) v3(105.33,20.34) v3(105.92,43.78) v3(105.92,36.28) v3(106.05,50.51) v3(106.68,25.23) v3(106.93,56.09) v3(106.92,42.51) v3(107.95,20.66) v3(108.19,31.09) v4(15.62,26.63) v4(16,23.84) v4(16.13,26.63) v4(16.51,23.84) v4(16.64,26.63) v4(17.02,23.84) v4(17.14,26.63) v4(18.03,52.03) v4(18.03,49.24) v4(18.54,52.03) v4(18.54,49.24) v4(20.57,52.03) v4(21.08,52.03) v4(22.1,52.03) v4(22.1,49.24) v4(22.1,22.57) v4(22.61,49.24) v4(22.61,22.95) v4(22.61,20.03) v4(22.61,19.52) v4(22.99,19.14) v4(23.11,15.58) v4(23.24,22.95) v4(23.24,20.03) v4(23.24,16.09) v4(23.37,18.63) v4(23.37,18.12) v4(23.37,17.61) v4(23.37,17.11) v4(23.62,49.24) v4(23.88,20.03) v4(24.13,49.24) v4(24.13,22.95) v4(24.38,35.77) v4(24.38,31.96) v4(24.51,20.03) v4(24.64,49.24) v4(24.77,34.63) v4(24.77,33.11) v4(24.77,22.95) v4(25.15,49.24) v4(25.4,22.95) v4(25.65,49.24) v4(25.78,35.01) v4(25.91,33.11) v4(26.16,49.24) v4(26.67,49.24) v4(26.8,22.82) v4(26.92,35.9) v4(26.92,34) v4(27.18,49.24) v4(27.81,22.82) v4(28.07,36.16) v4(28.07,34.25) v4(28.32,22.82) v4(28.45,20.03) v4(28.83,22.82) v4(29.21,20.03) v4(29.34,22.82) v4(29.59,19.52) v4(30.86,19.52) v4(31.11,22.82) v4(31.24,20.03) v4(31.62,22.82) v4(31.92,49.8) v4(31.88,20.03) v4(32.3,51.45) v4(32.56,49.8) v4(32.51,20.03) v4(32.94,51.45) v4(32.89,22.82) v4(33.19,49.8) v4(33.4,22.82) v4(33.4,19.77) v4(33.57,51.45) v4(33.83,49.8) v4(33.91,22.82) v4(34.16,51.27) v4(34.16,20.03) v4(34.33,50.05) v4(34.42,22.82) v4(34.84,50.05) v4(34.92,51.27) v4(34.92,22.82) v4(34.92,20.03) v4(35.43,22.82) v4(35.69,49.74) v4(35.69,20.03) v4(35.94,22.82) v4(36.45,22.82) v4(36.58,49.74) v4(36.96,22.82) v4(37.21,54.19) v4(37.34,49.74) v4(37.34,19.26) v4(37.97,54.19) v4(38.1,49.74) v4(38.73,54.19) v4(38.73,49.74) v4(39.5,54.19) v4(39.5,49.74) v4(40.26,54.19) v4(40.26,49.74) v4(41.02,54.19) v4(41.02,53.55) v4(41.02,50.38) v4(41.02,49.74) v4(41.78,53.55) v4(41.78,50.38) v4(42.54,53.55) v4(42.54,50.38) v4(43.18,53.68) v4(43.18,50.38) v4(43.94,53.68) v4(43.94,50.38) v4(44.58,50.38) v4(44.7,53.68) v4(45.34,53.55) v4(45.34,50.38) v4(45.97,53.55) v4(45.97,50.38) v4(46.48,53.17) v4(46.48,51.01) v4(47.12,53.17) v4(47.12,51.01) v4(47.12,5.42) v4(47.12,4.15) v4(47.62,4.02) v4(47.88,5.55) v4(48.13,61.43) v4(48.13,60.79) v4(48.26,4.02) v4(48.39,5.55) v4(48.51,61.81) v4(48.51,60.41) v4(48.71,11.34) v4(48.89,62.19) v4(48.89,60.03) v4(48.89,5.55) v4(48.89,4.02) v4(49.22,11.8) v4(49.28,62.57) v4(49.28,59.65) v4(49.4,5.42) v4(49.53,4.15) v4(49.66,59.27) v4(49.65,12.21) v4(49.93,62.65) v4(50.04,58.89) v4(50.04,5.42) v4(50.04,4.15) v4(50.11,12.64) v4(50.19,15.05) v4(50.16,14.32) v4(50.16,8.34) v4(50.16,7.83) v4(50.16,7.33) v4(50.16,6.82) v4(50.16,6.31) v4(50.42,58.38) v4(50.42,57.75) v4(50.42,57.11) v4(50.41,56.4) v4(50.44,15.58) v4(50.51,62.5) v4(50.67,5.42) v4(51.05,63.97) v4(51.05,63.46) v4(51.05,62.95) v4(51.05,62.44) v4(52.48,15.56) v4(52.7,14.95) v4(53.1,13.81) v4(53.08,12.39) v4(53.59,11.85) v4(53.85,65.37) v4(53.85,14.18) v4(54.07,11.45) v4(54.36,65.37) v4(54.48,58.63) v4(54.48,58.13) v4(54.48,57.62) v4(54.63,10.99) v4(54.61,8.34) v4(54.61,7.83) v4(54.61,7.33) v4(54.61,6.82) v4(54.61,6.31) v4(54.86,65.24) v4(54.86,13.17) v4(54.99,59.02) v4(55.29,58.44) v4(55.37,64.98) v4(55.37,59.4) v4(55.54,28.21) v4(55.63,64.22) v4(55.63,63.71) v4(55.63,63.21) v4(55.63,62.7) v4(55.7,66.61) v4(55.75,59.78) v4(55.88,62.19) v4(56.13,60.16) v4(56.21,66.1) v4(56.26,61.81) v4(56.39,12.66) v4(56.52,60.54) v4(56.64,61.43) v4(56.56,58.69) v4(56.85,65.85) v4(56.9,60.92) v4(57.07,28.21) v4(57.53,63.84) v4(57.83,58.69) v4(57.91,12.66) v4(58.29,65.24) v4(58.29,63.84) v4(58.59,28.21) v4(59.05,65.24) v4(59.05,63.84) v4(59.1,58.69) v4(59.69,65.24) v4(59.69,63.84) v4(59.94,12.66) v4(60.12,58.69) v4(60.32,65.24) v4(60.32,63.84) v4(61.47,12.66) v4(61.64,58.69) v4(62.15,42.43) v4(62.4,28.21) v4(62.91,58.69) v4(62.99,12.66) v4(63.93,28.21) v4(64.18,58.69) v4(64.18,42.94) v4(64.52,12.66) v4(65.45,58.69) v4(65.96,28.21) v4(66.04,12.66) v4(66.72,58.69) v4(66.72,42.94) v4(67.48,28.21) v4(67.56,12.66) v4(67.99,58.69) v4(68.24,42.94) v4(68.58,12.66) v4(69.01,28.21) v4(69.26,58.69) v4(69.6,12.66) v4(69.77,42.94) v4(70.53,58.69) v4(70.53,28.21) v4(70.61,12.66) v4(71.29,42.94) v4(71.63,12.66) v4(72.05,28.21) v4(72.64,12.66) v4(72.82,42.94) v4(73.58,28.21) v4(73.66,12.66) v4(73.83,58.69) v4(74.34,42.94) v4(74.68,12.66) v4(75.36,28.21) v4(75.69,12.66) v4(75.86,42.94) v4(76.71,12.66) v4(77.39,42.94) v4(77.72,12.66) v4(77.98,28.28) v4(78.74,12.66) v4(78.91,57.93) v4(78.91,42.94) v4(78.99,29.3) v4(79.76,11.64) v4(79.93,58.44) v4(80.01,30.31) v4(80.18,42.43) v4(80.77,11.64) v4(81.2,41.42) v4(81.45,31.77) v4(81.79,11.64) v4(82.21,40.4) v4(82.47,32.78) v4(82.72,58.44) v4(82.8,11.64) v4(83.48,39.13) v4(83.82,11.64) v4(83.99,58.44) v4(84.84,11.64) v4(85.01,58.44) v4(85.85,11.64) v4(87.55,58.44) v4(92.63,59.45) v4(94.91,60.98) v4(95.68,49.04) v4(96.44,60.98) v4(97.07,49.04) v4(97.45,49.8) v4(97.96,60.98) v4(98.34,49.04) v4(98.72,15.26) v4(98.72,10.56) v4(99.36,18.43) v4(99.49,60.98) v4(99.61,15.76) v4(99.74,34.94) v4(99.74,33.29) v4(99.99,51.07) v4(99.99,12.72) v4(100.5,59.96) v4(100.5,52.59) v4(100.76,48.91) v4(100.88,28.08) v4(101.52,58.94) v4(101.52,53.61) v4(101.77,47.9) v4(101.9,46.24) v4(101.9,44.72) v4(101.9,43.2) v4(101.9,41.67) v4(101.9,39.77) v4(101.9,38.24) v4(101.9,36.47) v4(101.9,34.94) v4(101.9,33.29) v4(102.03,57.67) v4(102.03,56.15) v4(102.03,54.63) v5(0.64,55.78) v5(0.64,54) v5(0.64,47.27) v5(0.64,45.49) v5(0.64,30.38) v5(0.64,28.6) v5(0.64,21.87) v5(0.64,20.09) v5(1.91,55.78) v5(1.91,54) v5(1.91,47.27) v5(1.91,45.49) v5(1.91,30.38) v5(1.91,28.6) v5(1.91,21.87) v5(1.91,20.09) v5(3.17,55.78) v5(3.17,54) v5(3.17,47.27) v5(3.17,45.49) v5(3.17,30.38) v5(3.17,28.6) v5(3.17,21.87) v5(3.17,20.09) v5(4.44,55.78) v5(4.44,54) v5(4.44,47.27) v5(4.44,45.49) v5(4.44,30.38) v5(4.44,28.6) v5(4.44,21.87) v5(4.44,20.09) v6(13.21,37.04) v6(13.97,36.41) v6(14.61,35.65) v6(16.76,37.17) v6(16.89,35.14) v6(17.78,38.06) v6(18.03,36.03) v6(19.05,36.92) v6(42.29,28.79) v6(42.46,54.88) v6(42.62,38.19) v6(42.67,28.41) v6(42.84,54.5) v6(42.79,30.83) v6(43.05,28.03) v6(43.18,54.01) v6(43.18,53.37) v6(43.18,52.74) v6(43.18,52.1) v6(43.18,51.49) v6(43.18,50.86) v6(43.26,38.14) v6(43.2,30.35) v6(43.3,35.12) v6(43.58,36.01) v6(43.68,50.37) v6(44.13,49.92) v6(44.2,34.25) v6(44.32,39.94) v6(44.54,28.72) v6(44.7,34) v6(44.77,49.27) v6(44.8,31.74) v6(44.96,28.24) v6(45.06,48.77) v6(45.06,48.14) v6(45.06,47.5) v6(45.06,46.87) v6(45.06,46.23) v6(45.06,45.6) v6(45.06,44.96) v6(45.06,44.28) v6(45.06,43.64) v6(45.21,54.01) v6(45.21,53.37) v6(45.21,52.74) v6(45.22,43.02) v6(45.28,38.38) v6(45.37,27.76) v6(45.44,27.09) v6(45.44,26.45) v6(45.44,25.82) v6(45.44,24.42) v6(45.44,23.78) v6(45.44,23.15) v6(45.44,22.51) v6(45.44,21.88) v6(45.44,21.24) v6(45.44,20.61) v6(45.44,19.97) v6(45.44,19.34) v6(45.44,18.7) v6(45.44,18.07) v6(45.44,17.43) v6(45.44,16.72) v6(45.44,16.09) v6(45.44,15.45) v6(45.44,14.82) v6(45.44,14.18) v6(45.44,13.55) v6(45.44,12.91) v6(45.44,12.28) v6(45.44,11.64) v6(45.44,11.01) v6(45.44,10.37) v6(45.55,54.54) v6(45.48,35.77) v6(45.64,9.8) v6(45.67,42.57) v6(45.76,30.85) v6(45.89,51.06) v6(45.92,38.38) v6(46.02,54.97) v6(46.12,42.12) v6(46.12,35.77) v6(46.07,9.36) v6(46.34,50.61) v6(46.27,30.56) v6(46.4,56.79) v6(46.39,56.14) v6(46.37,55.5) v6(46.48,40.91) v6(46.48,40.28) v6(46.48,39.64) v6(46.48,39.01) v6(46.48,38.37) v6(46.5,8.91) v6(46.57,29.99) v6(46.75,35.77) v6(46.81,50.14) v6(46.99,29.51) v6(47.12,49.49) v6(47.12,48.24) v6(47.12,47.6) v6(47.12,46.97) v6(47.12,46.33) v6(47.12,45.7) v6(47.12,45.06) v6(47.12,44.43) v6(47.09,8.7) v6(47.23,43.91) v6(47.37,35.93) v6(47.4,29.03) v6(47.5,28.41) v6(47.5,27.77) v6(47.5,27.14) v6(47.5,26.5) v6(47.5,23.33) v6(47.5,22.69) v6(47.5,22.06) v6(47.5,21.42) v6(47.5,20.79) v6(47.5,20.15) v6(47.5,19.52) v6(47.5,18.88) v6(47.5,18.25) v6(47.5,17.61) v6(47.5,16.98) v6(47.5,16.34) v6(47.5,15.07) v6(47.5,13.17) v6(47.5,12.53) v6(47.5,11.9) v6(47.5,11.26) v6(47.67,43.46) v6(47.73,8.7) v6(47.83,36.37) v6(47.88,10.76) v6(48.12,43.01) v6(48.25,51.19) v6(48.27,36.82) v6(48.36,8.7) v6(48.48,42.49) v6(48.51,41.85) v6(48.51,41.22) v6(48.51,40.58) v6(48.51,39.95) v6(48.51,39.31) v6(48.51,38.68) v6(48.51,38.04) v6(48.51,37.41) v6(48.52,10.76) v6(48.66,8.07) v6(49.15,10.76) v6(49.4,7.78) v6(49.79,10.76) v6(50.04,7.78) v6(50.42,10.75) v6(50.67,7.78) v6(51,10.49) v6(51.31,7.78) v6(51.7,9.94) v6(51.94,7.78) v6(52.24,9.54) v6(52.52,8.12) v6(52.62,9.21) v6(52.75,8.73) v6(56.71,45.34) v6(57.44,46.05) v6(57.95,46.57) v6(58.42,48.73) v6(58.96,46.57) v6(59.97,48.86) v6(59.98,46.57) v6(60.98,48.86) v6(60.99,46.57) v6(62,48.86) v6(62.01,46.57) v6(63.02,48.86) v6(63.03,46.57) v6(64.03,48.86) v6(64.04,46.57) v6(65.05,48.86) v6(65.06,46.57) v6(66.06,48.86) v6(66.07,46.57) v6(67.08,48.86) v6(67.09,46.57) v6(68.03,49.21) v6(68.11,46.57) v6(68.75,49.93) v6(69.03,46.98) v6(69.47,50.65) v6(69.75,47.7) v6(70.19,51.37) v6(70.47,48.42) v6(70.91,52.09) v6(71.19,49.14) v6(71.62,52.81) v6(71.91,49.86) v6(72.59,53.11) v6(72.63,50.57) v6(73.61,53.11) v6(73.61,50.82) v6(74.63,53.11) v6(74.63,50.82) v6(75.64,53.11) v6(75.64,50.82) v6(76.66,53.11) v6(76.66,50.82) v6(77.67,53.11) v6(77.67,50.82) v6(78.62,50.44) v6(78.69,53.11) v6(79.63,50.42) v6(79.97,53) v6(82.8,56.35) v6(82.8,55.33) v6(82.8,54.32) v6(82.8,53.3) v6(82.8,52.28) v6(82.8,51.27) v6(82.8,50.25) v6(83.31,49.24) v6(83.31,47.71) v6(83.31,46.7) v6(83.31,45.68) v6(83.31,44.66) v6(83.31,43.65) v6(83.31,42.63) v6(83.31,41.62) v6(83.31,40.6) v6(83.31,39.58) v6(83.31,38.57) v6(83.82,57.36) v6(85.34,57.87) v6(85.34,54.32) v6(85.34,52.79) v6(85.85,55.33) v6(85.85,51.78) v6(85.85,47.71) v6(85.85,46.7) v6(85.85,45.68) v6(85.85,44.66) v6(85.85,43.65) v6(85.85,42.63) v6(85.85,41.62) v6(85.85,40.6) v6(85.85,39.58) v6(85.85,38.57)
